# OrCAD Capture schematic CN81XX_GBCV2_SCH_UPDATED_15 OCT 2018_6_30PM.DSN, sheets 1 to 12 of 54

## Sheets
1 53.IO-EXPANDER: size B; title: IO-EXPANDER; rev: 1.0
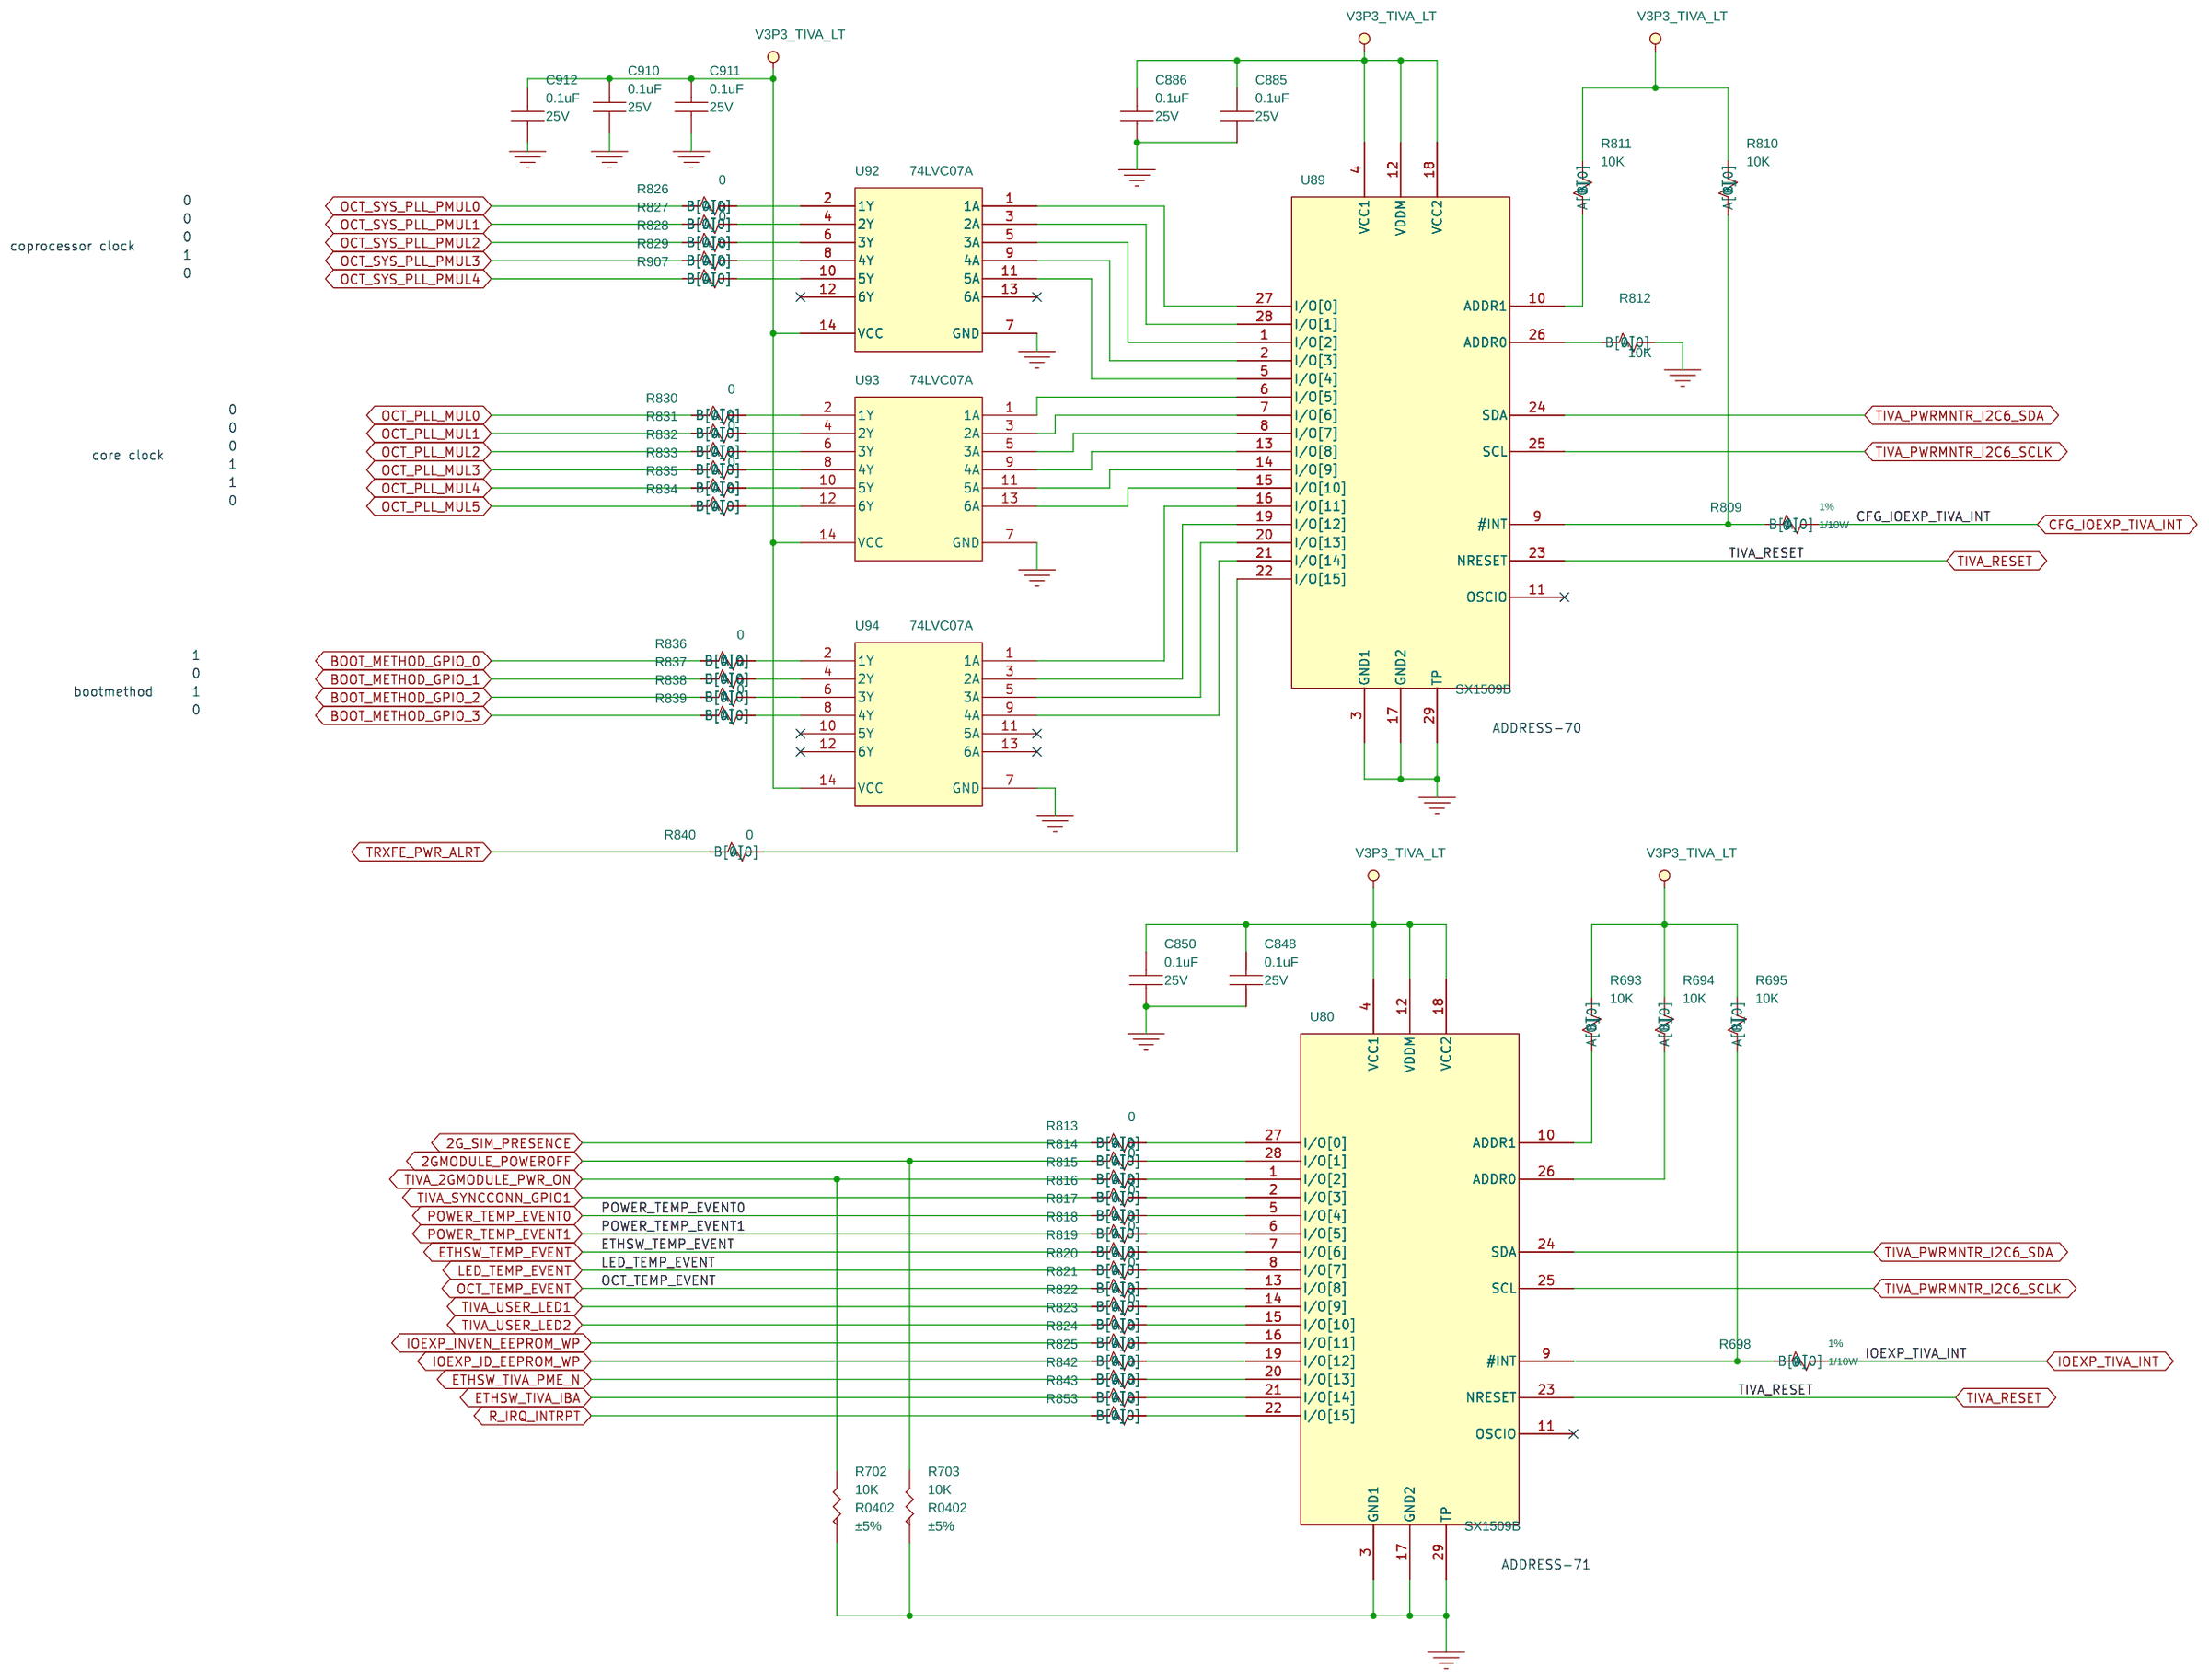
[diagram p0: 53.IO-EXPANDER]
2 54. SuperCap Back-Up: size A; title: TIVA BackUp Power
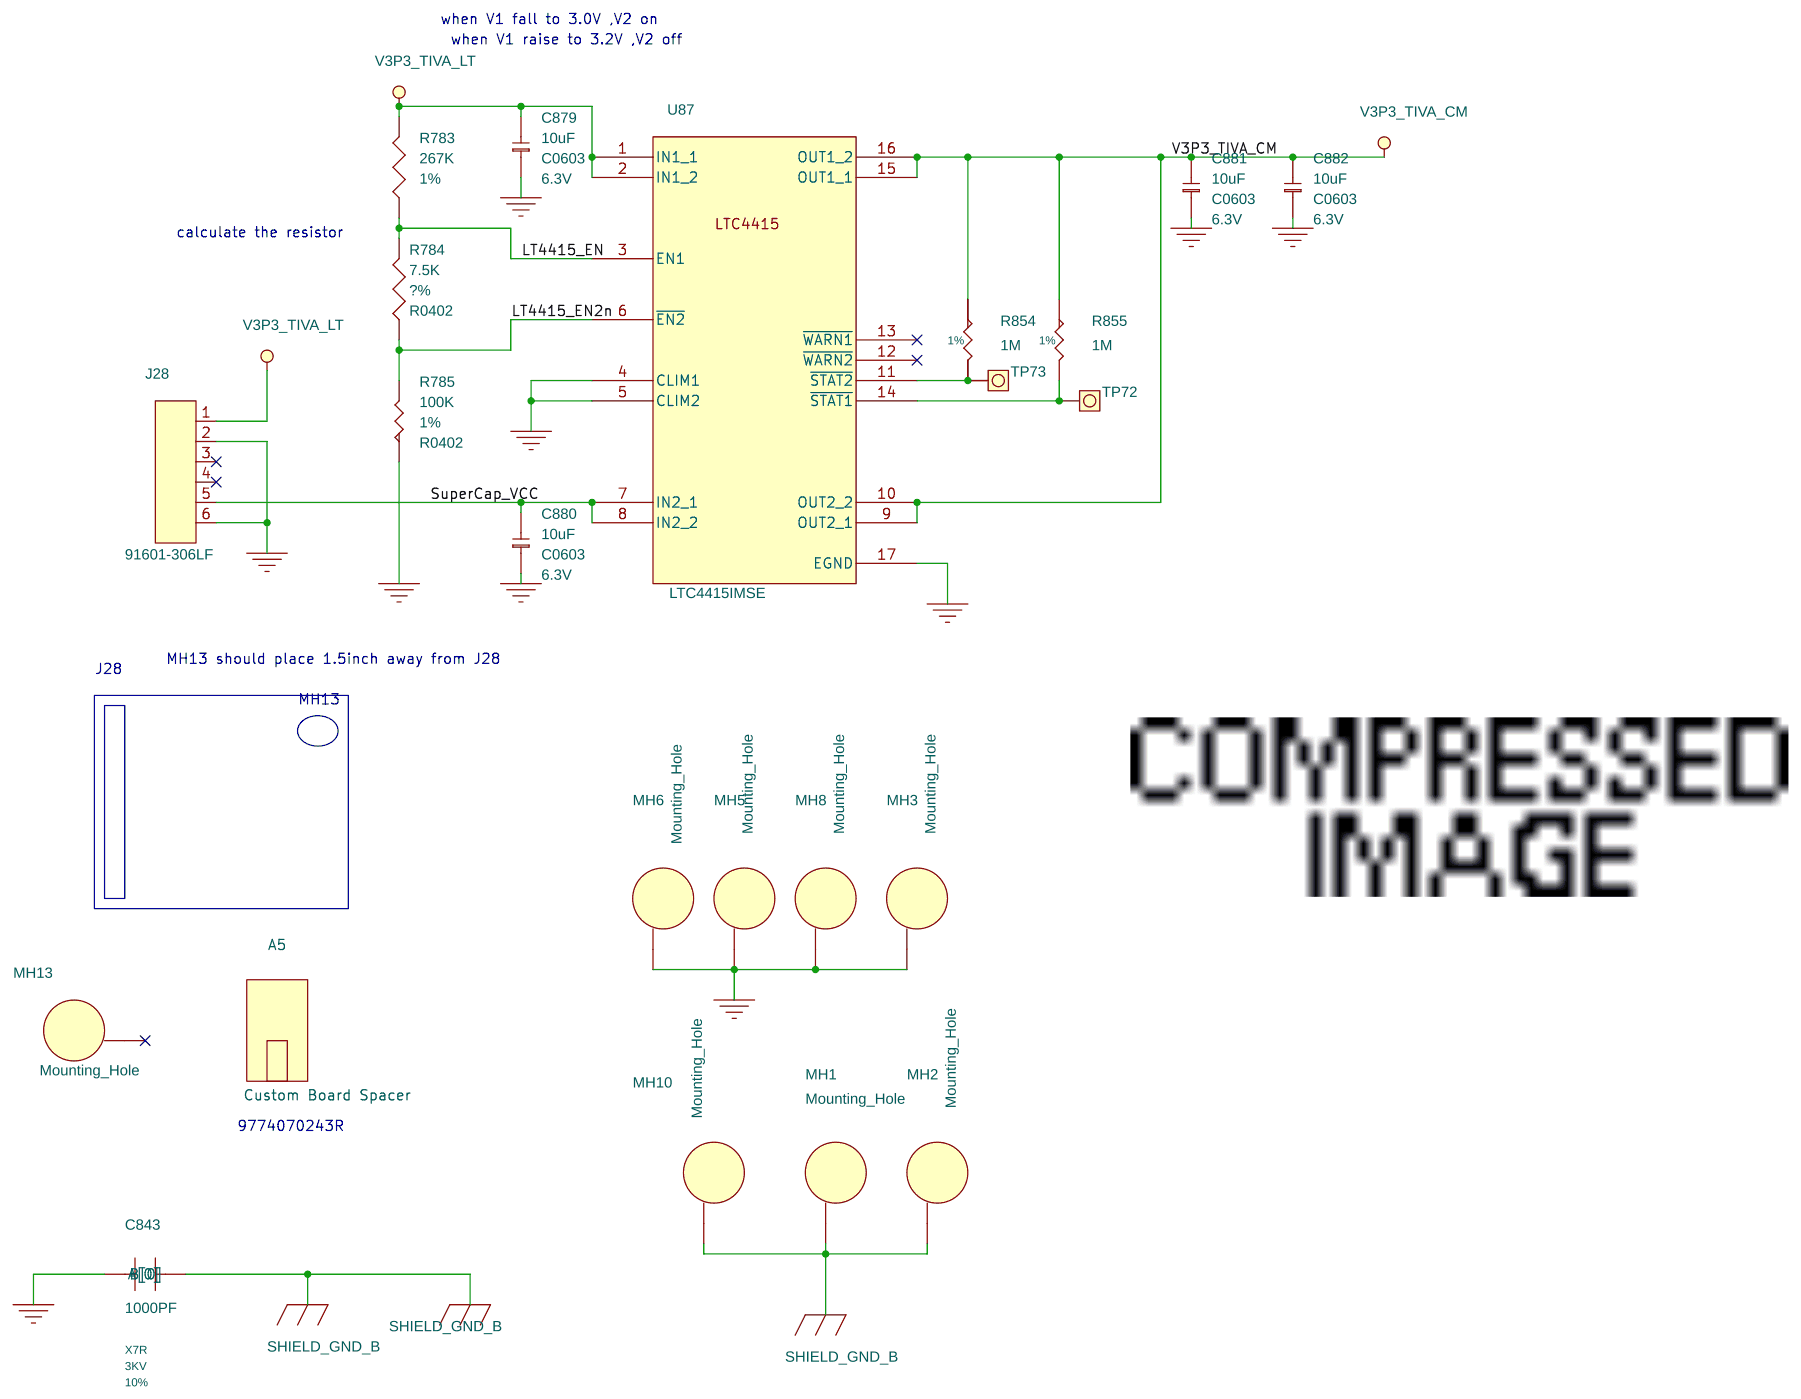
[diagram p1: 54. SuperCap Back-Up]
3 01.CN81XX COVER PAGE: title: CN81XX COVER PAGE
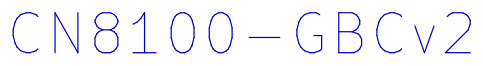
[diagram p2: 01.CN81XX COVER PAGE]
4 02.TABLE OF CONTENTS: title: TABLE OF CONTENTS
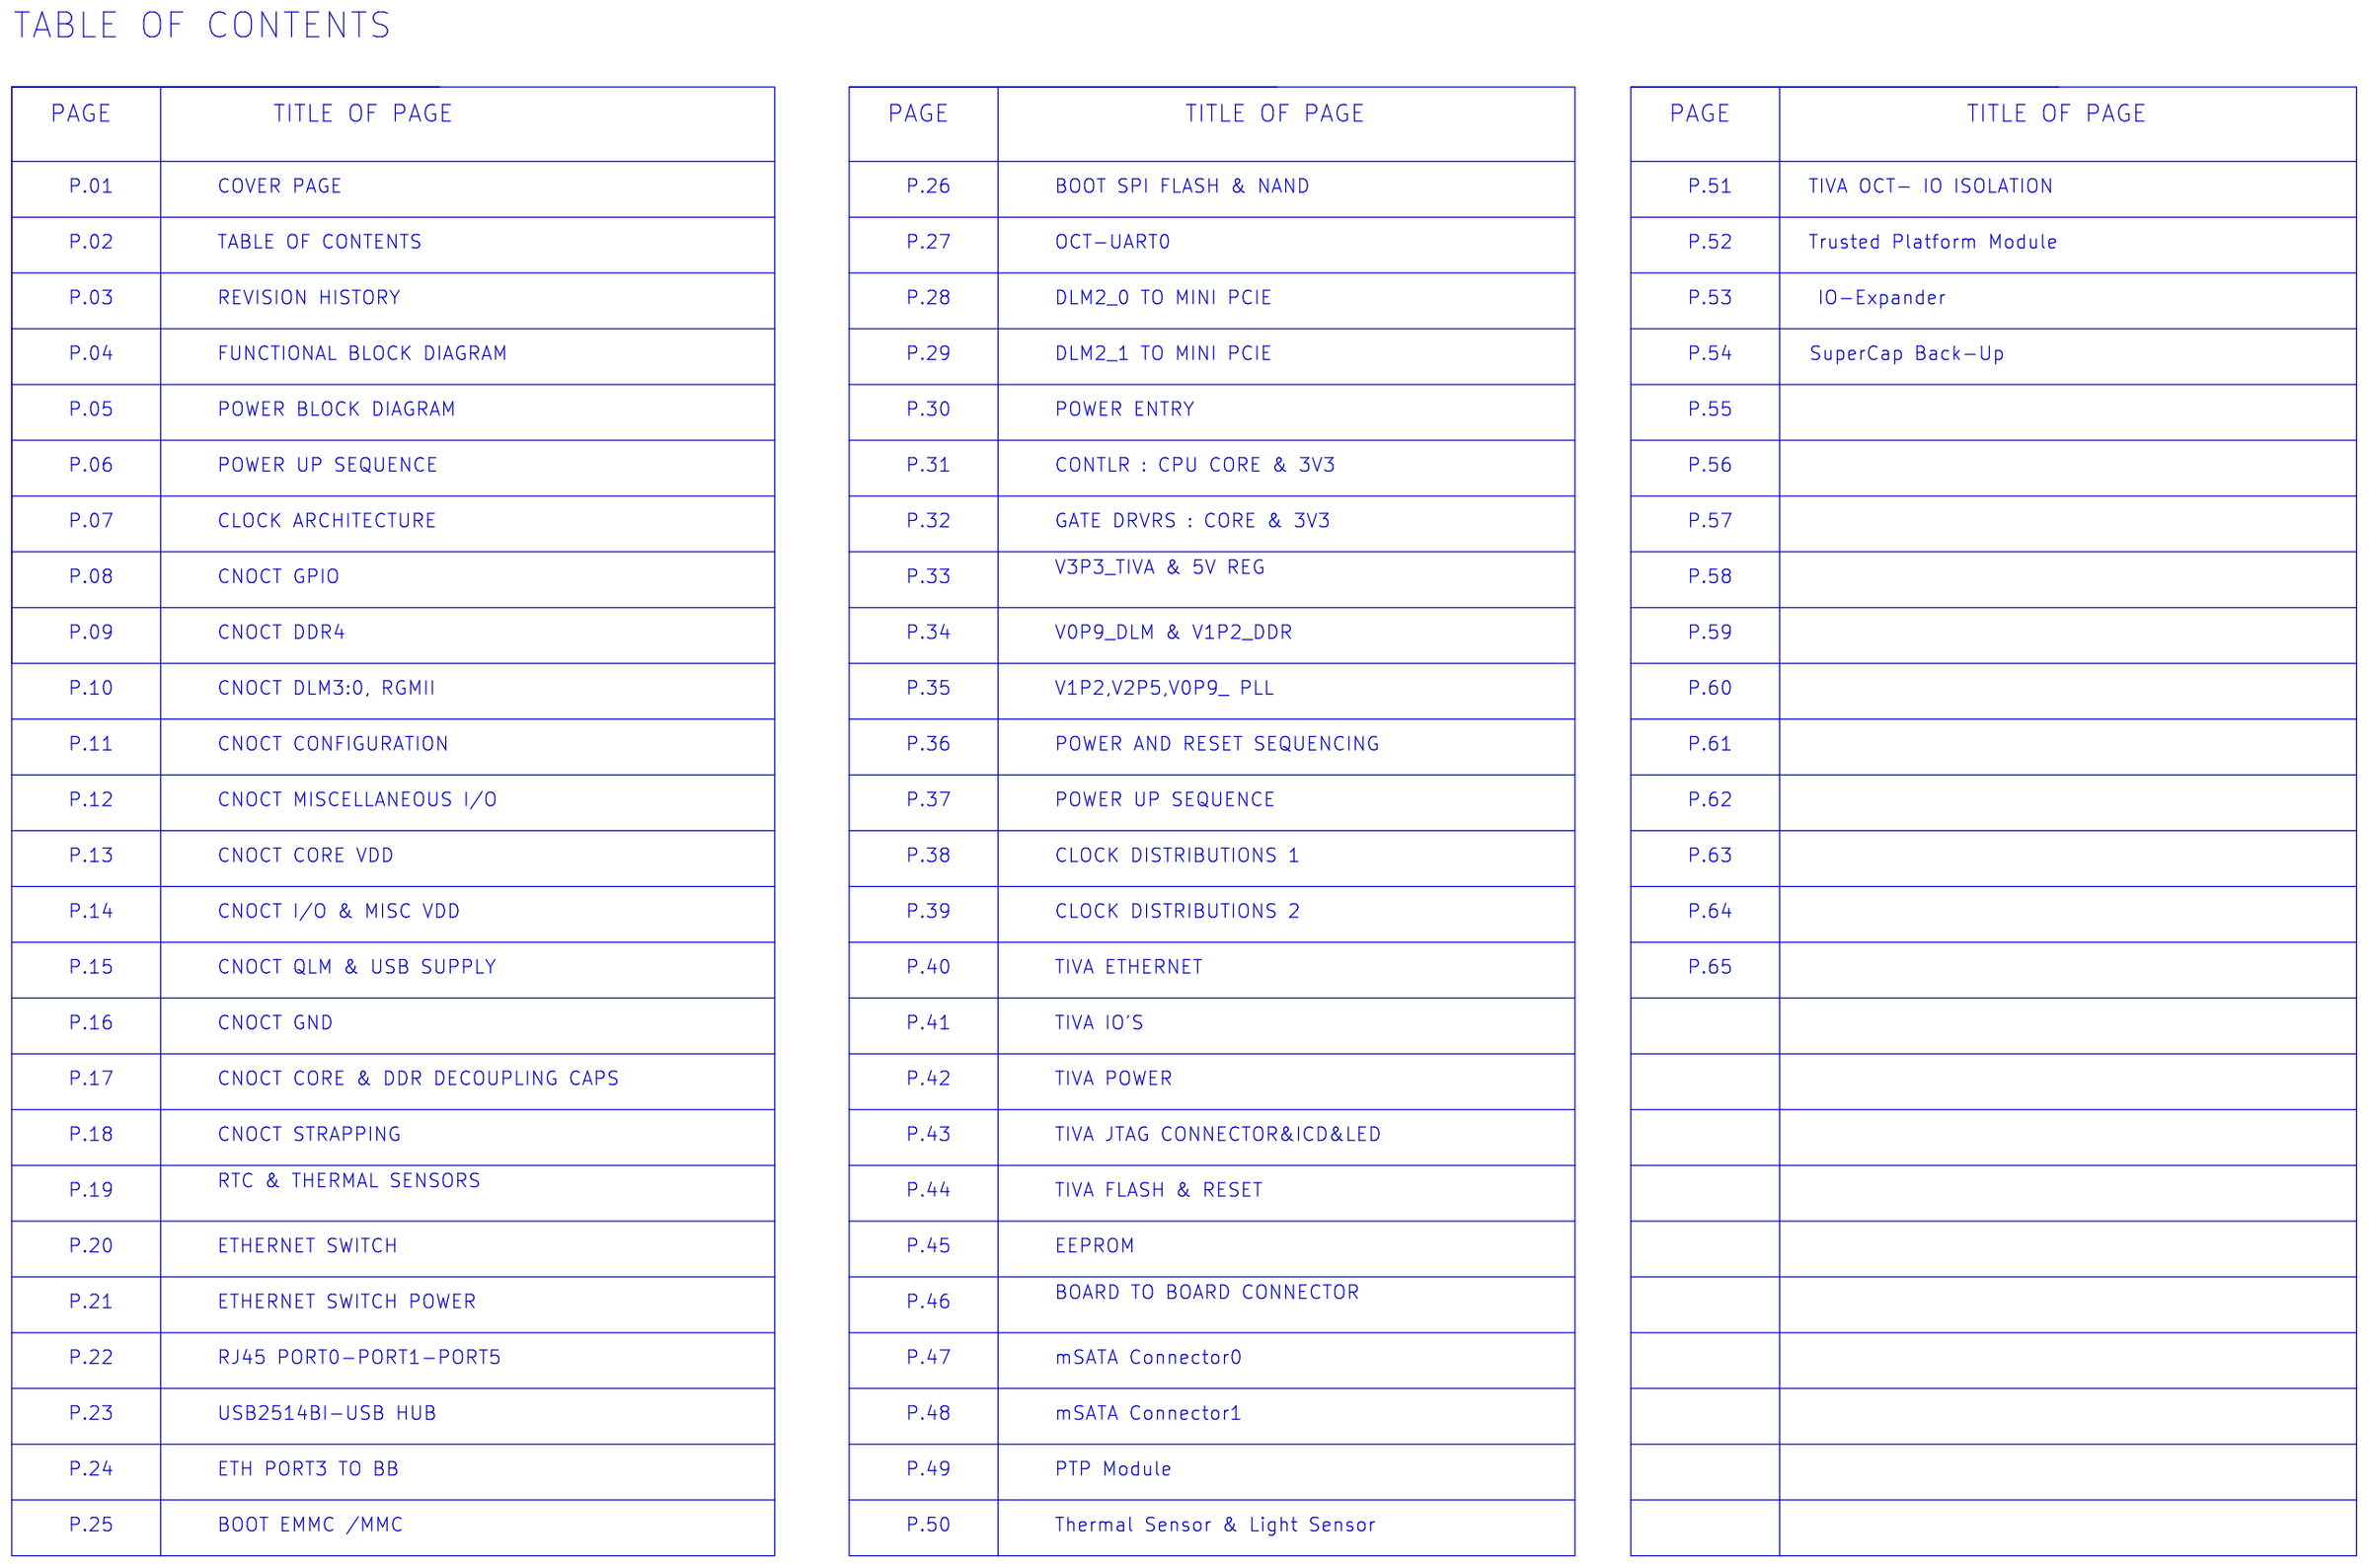
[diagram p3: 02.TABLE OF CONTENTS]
5 03.REVISION HISTORY: title: REVISION HISTORY
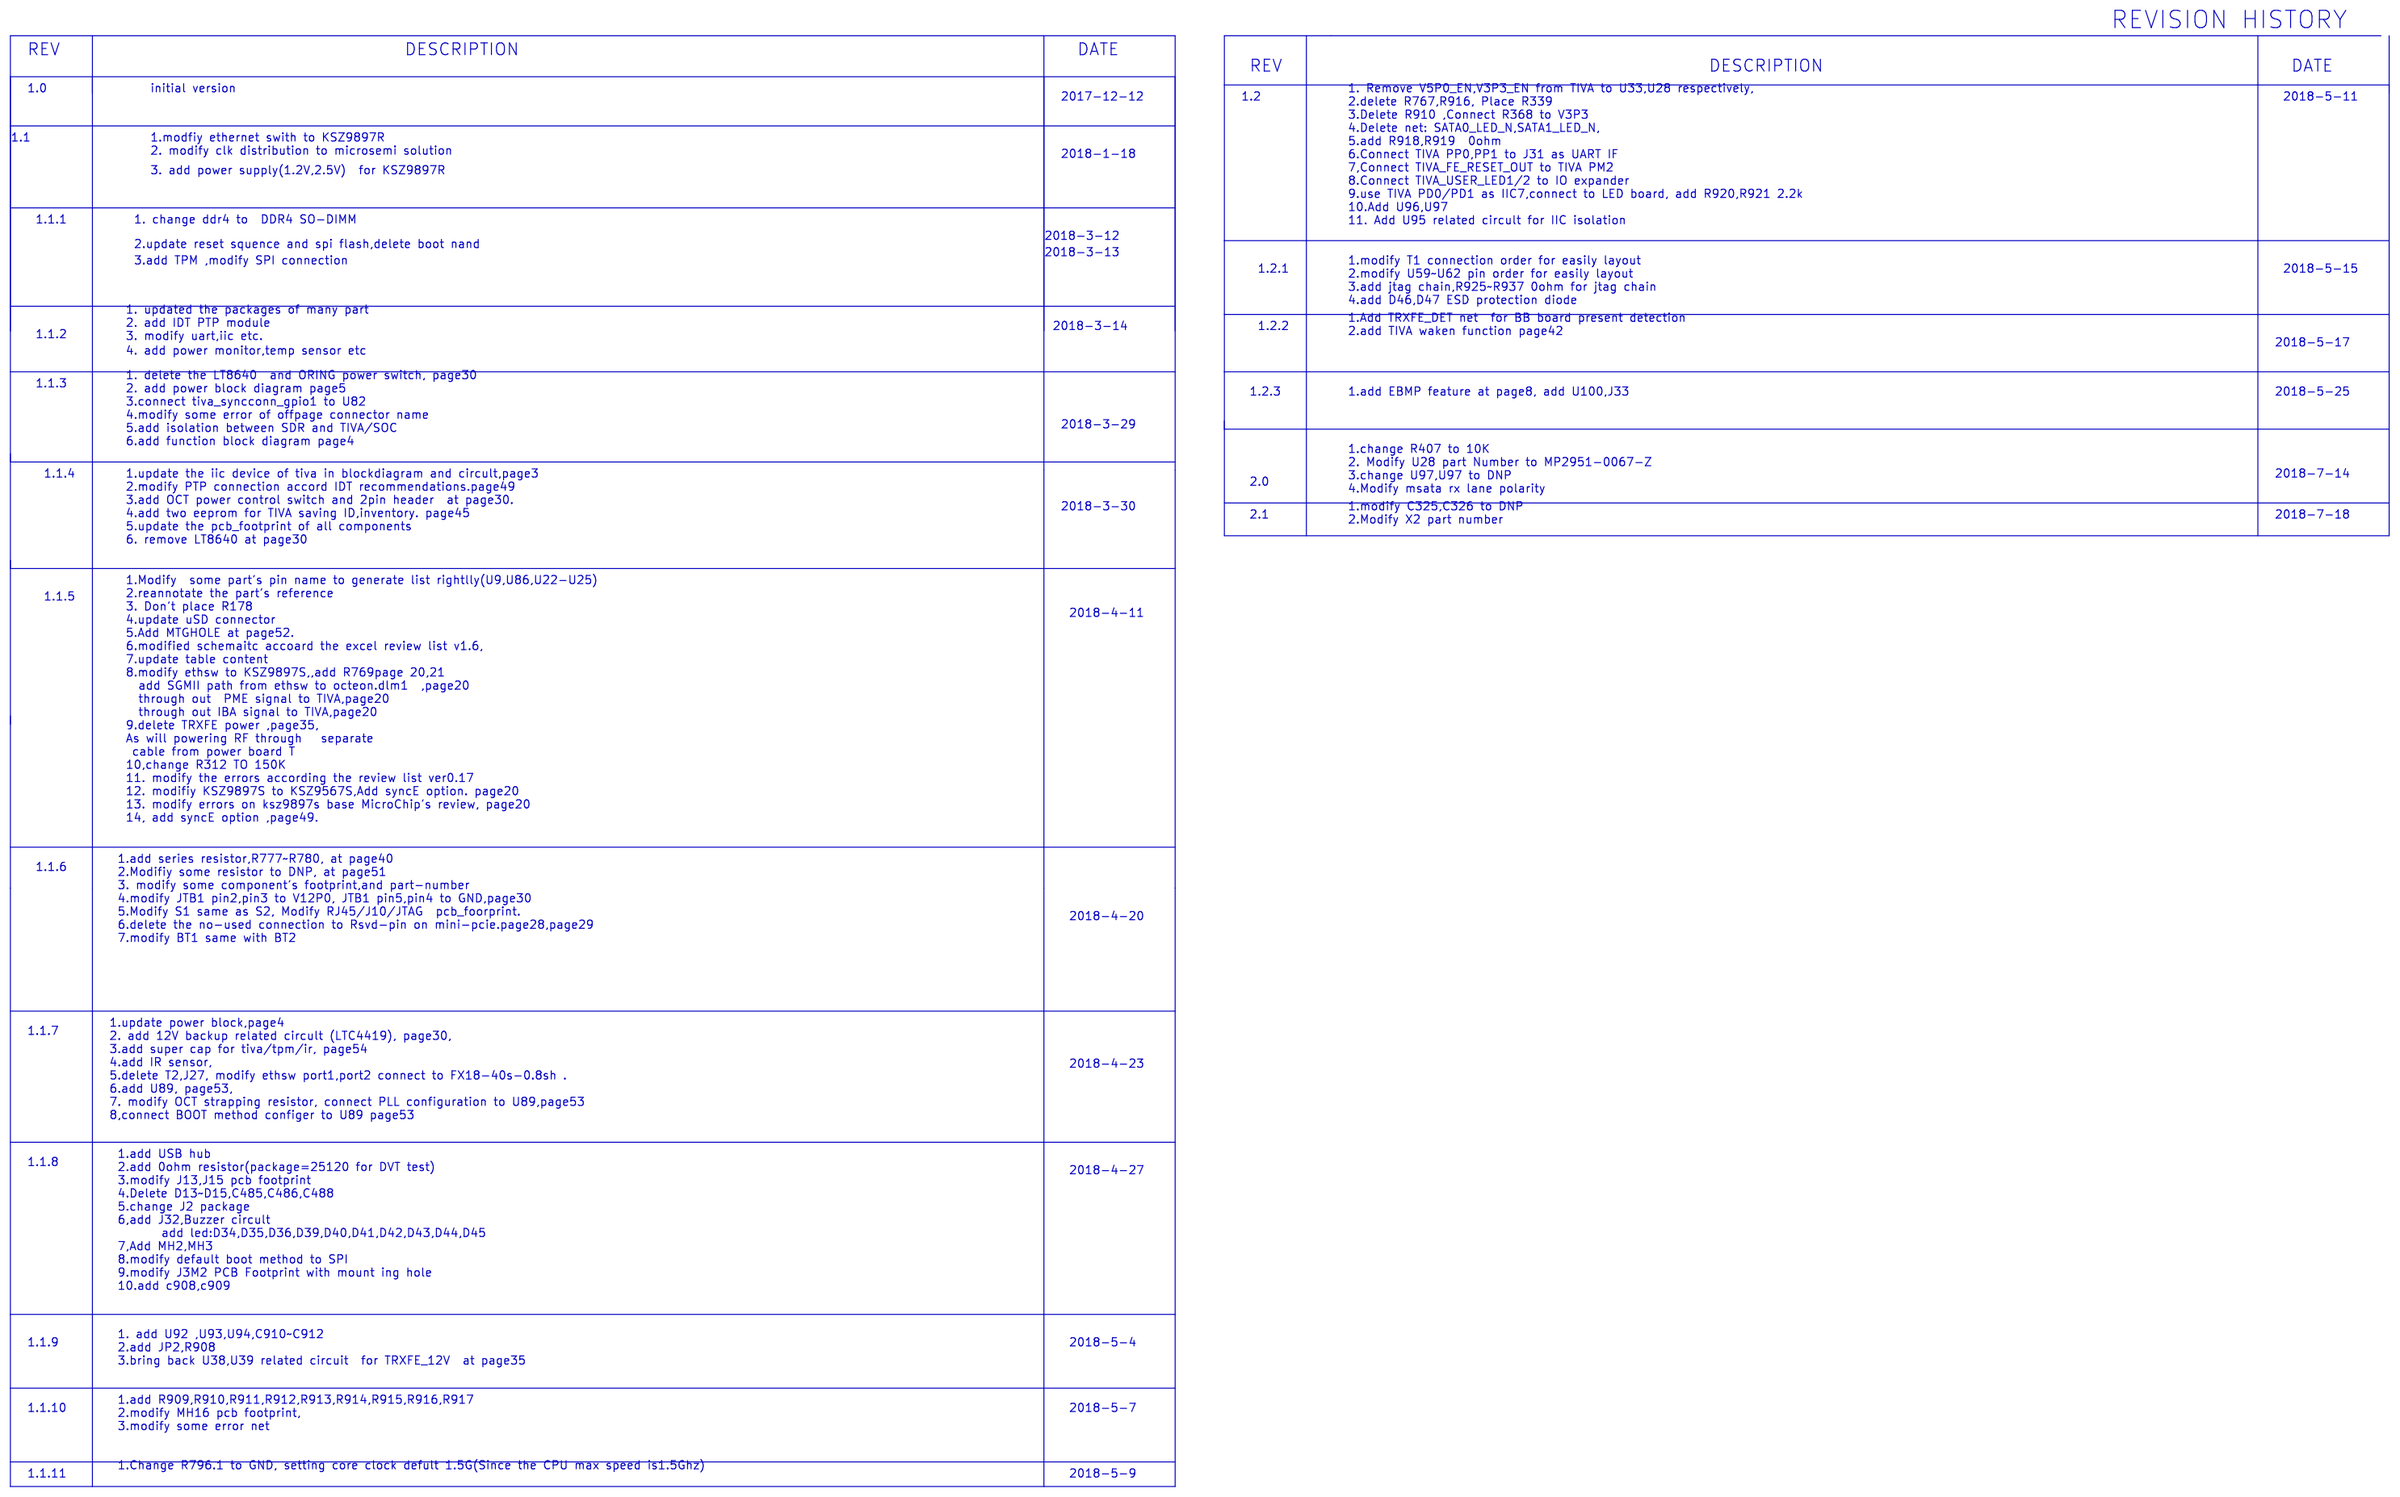
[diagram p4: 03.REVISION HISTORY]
6 04.FUNCTIONAL BLOCK DIAGRAM: title: FUNCTIONAL BLOCK DIAGRAM
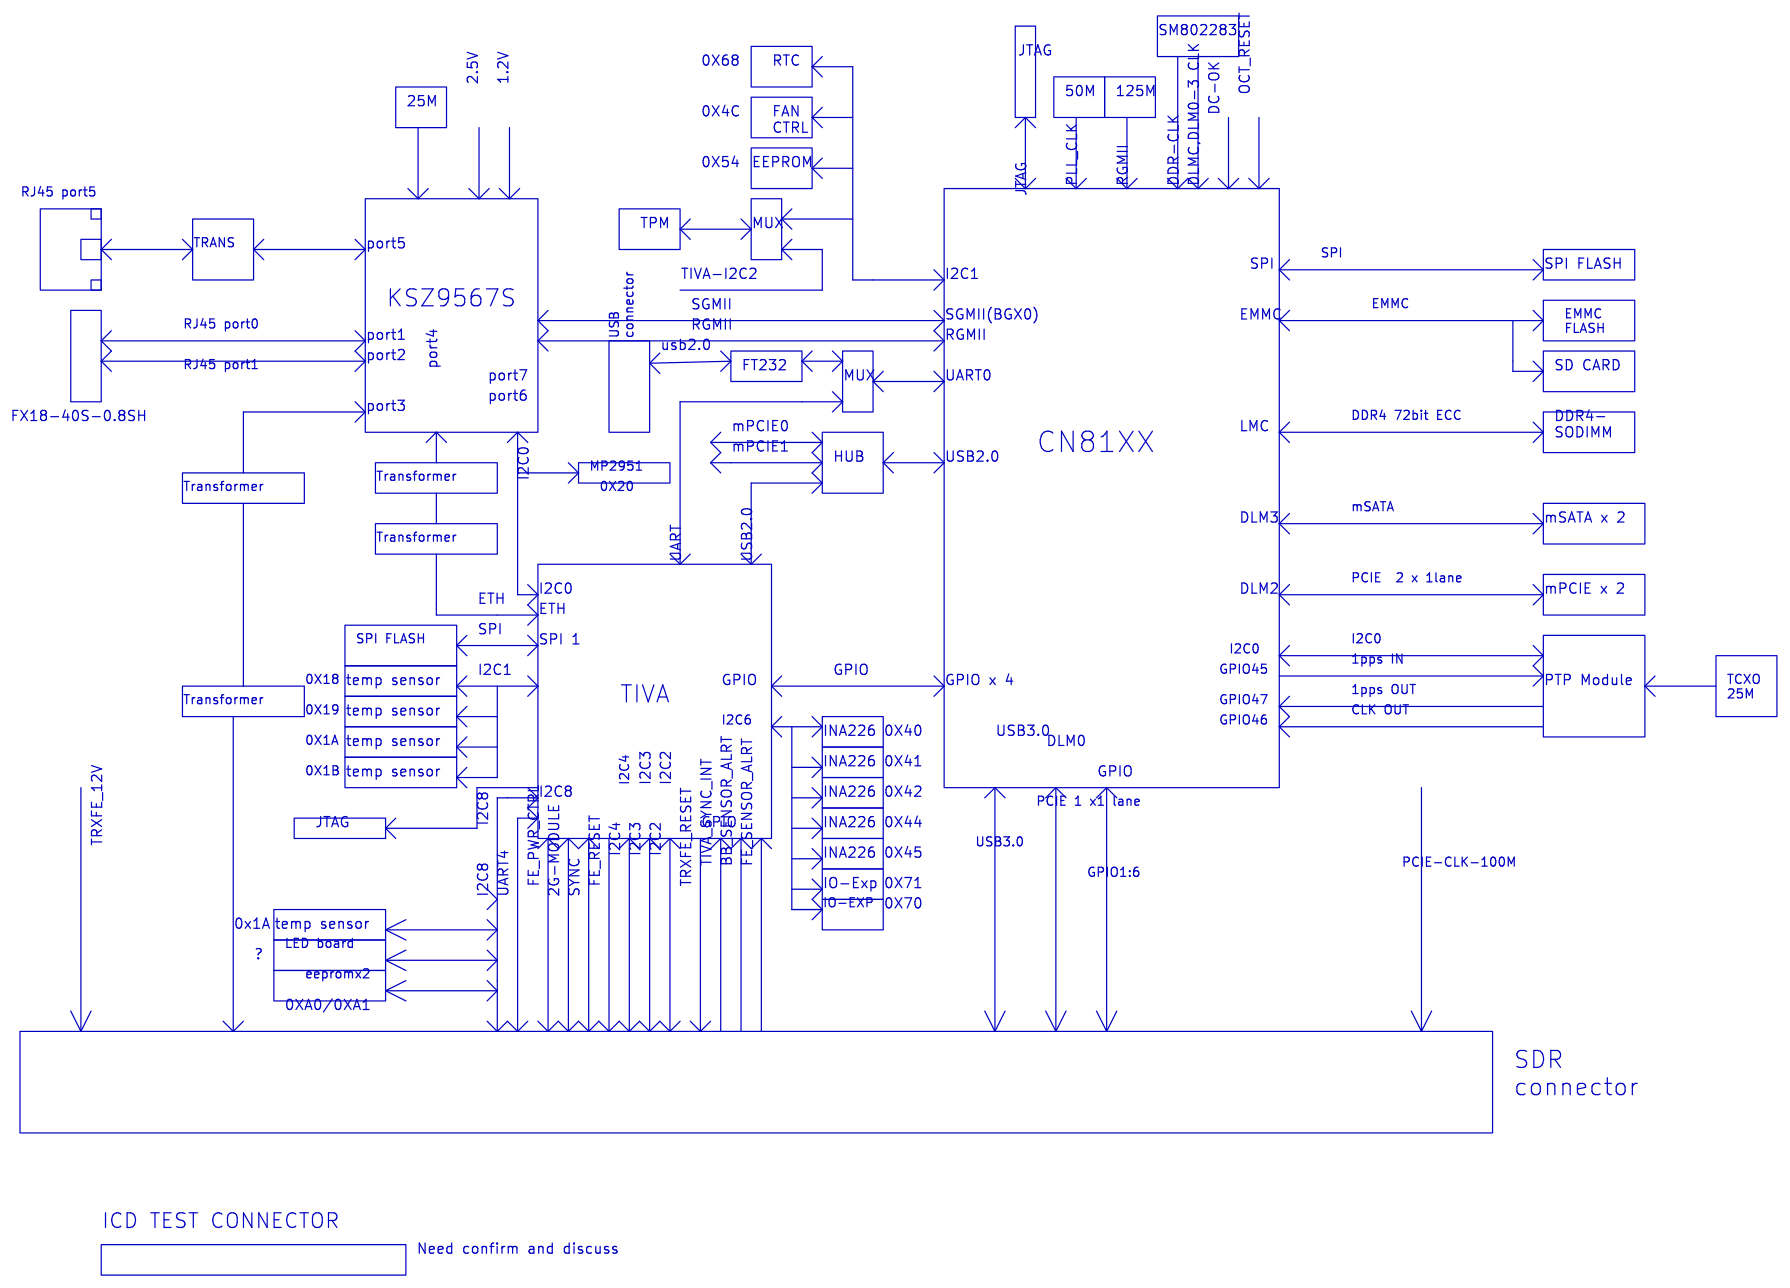
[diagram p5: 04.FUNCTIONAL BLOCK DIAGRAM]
7 05.POWER BLOCK DIAGRAM: title: POWER DIAGRAMS
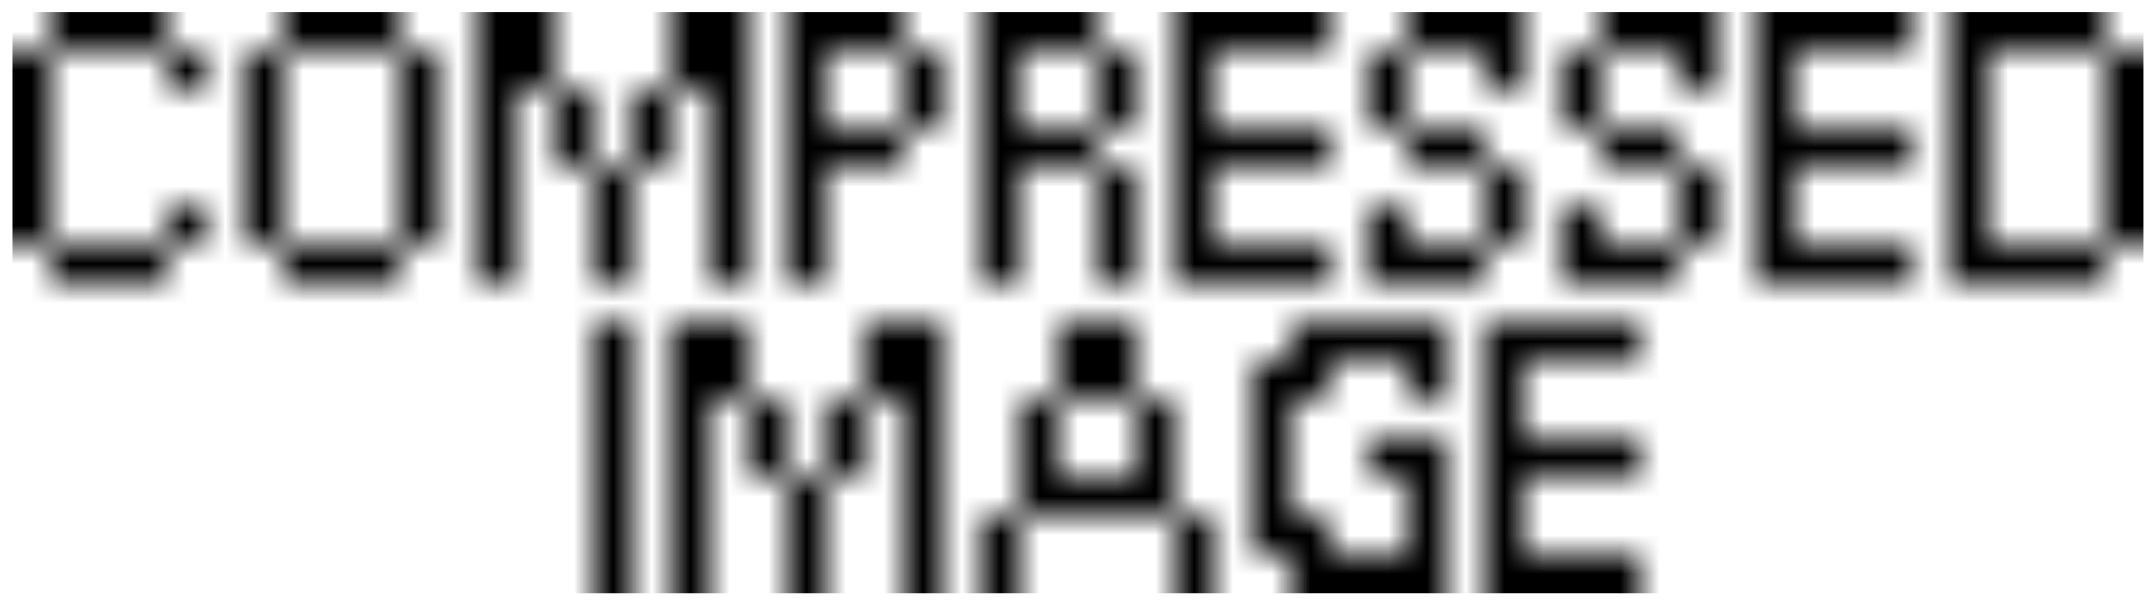
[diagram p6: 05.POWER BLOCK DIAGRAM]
8 06.POWER UP SEQUENCE: title: POWER UP SEQUENCE BLOCK
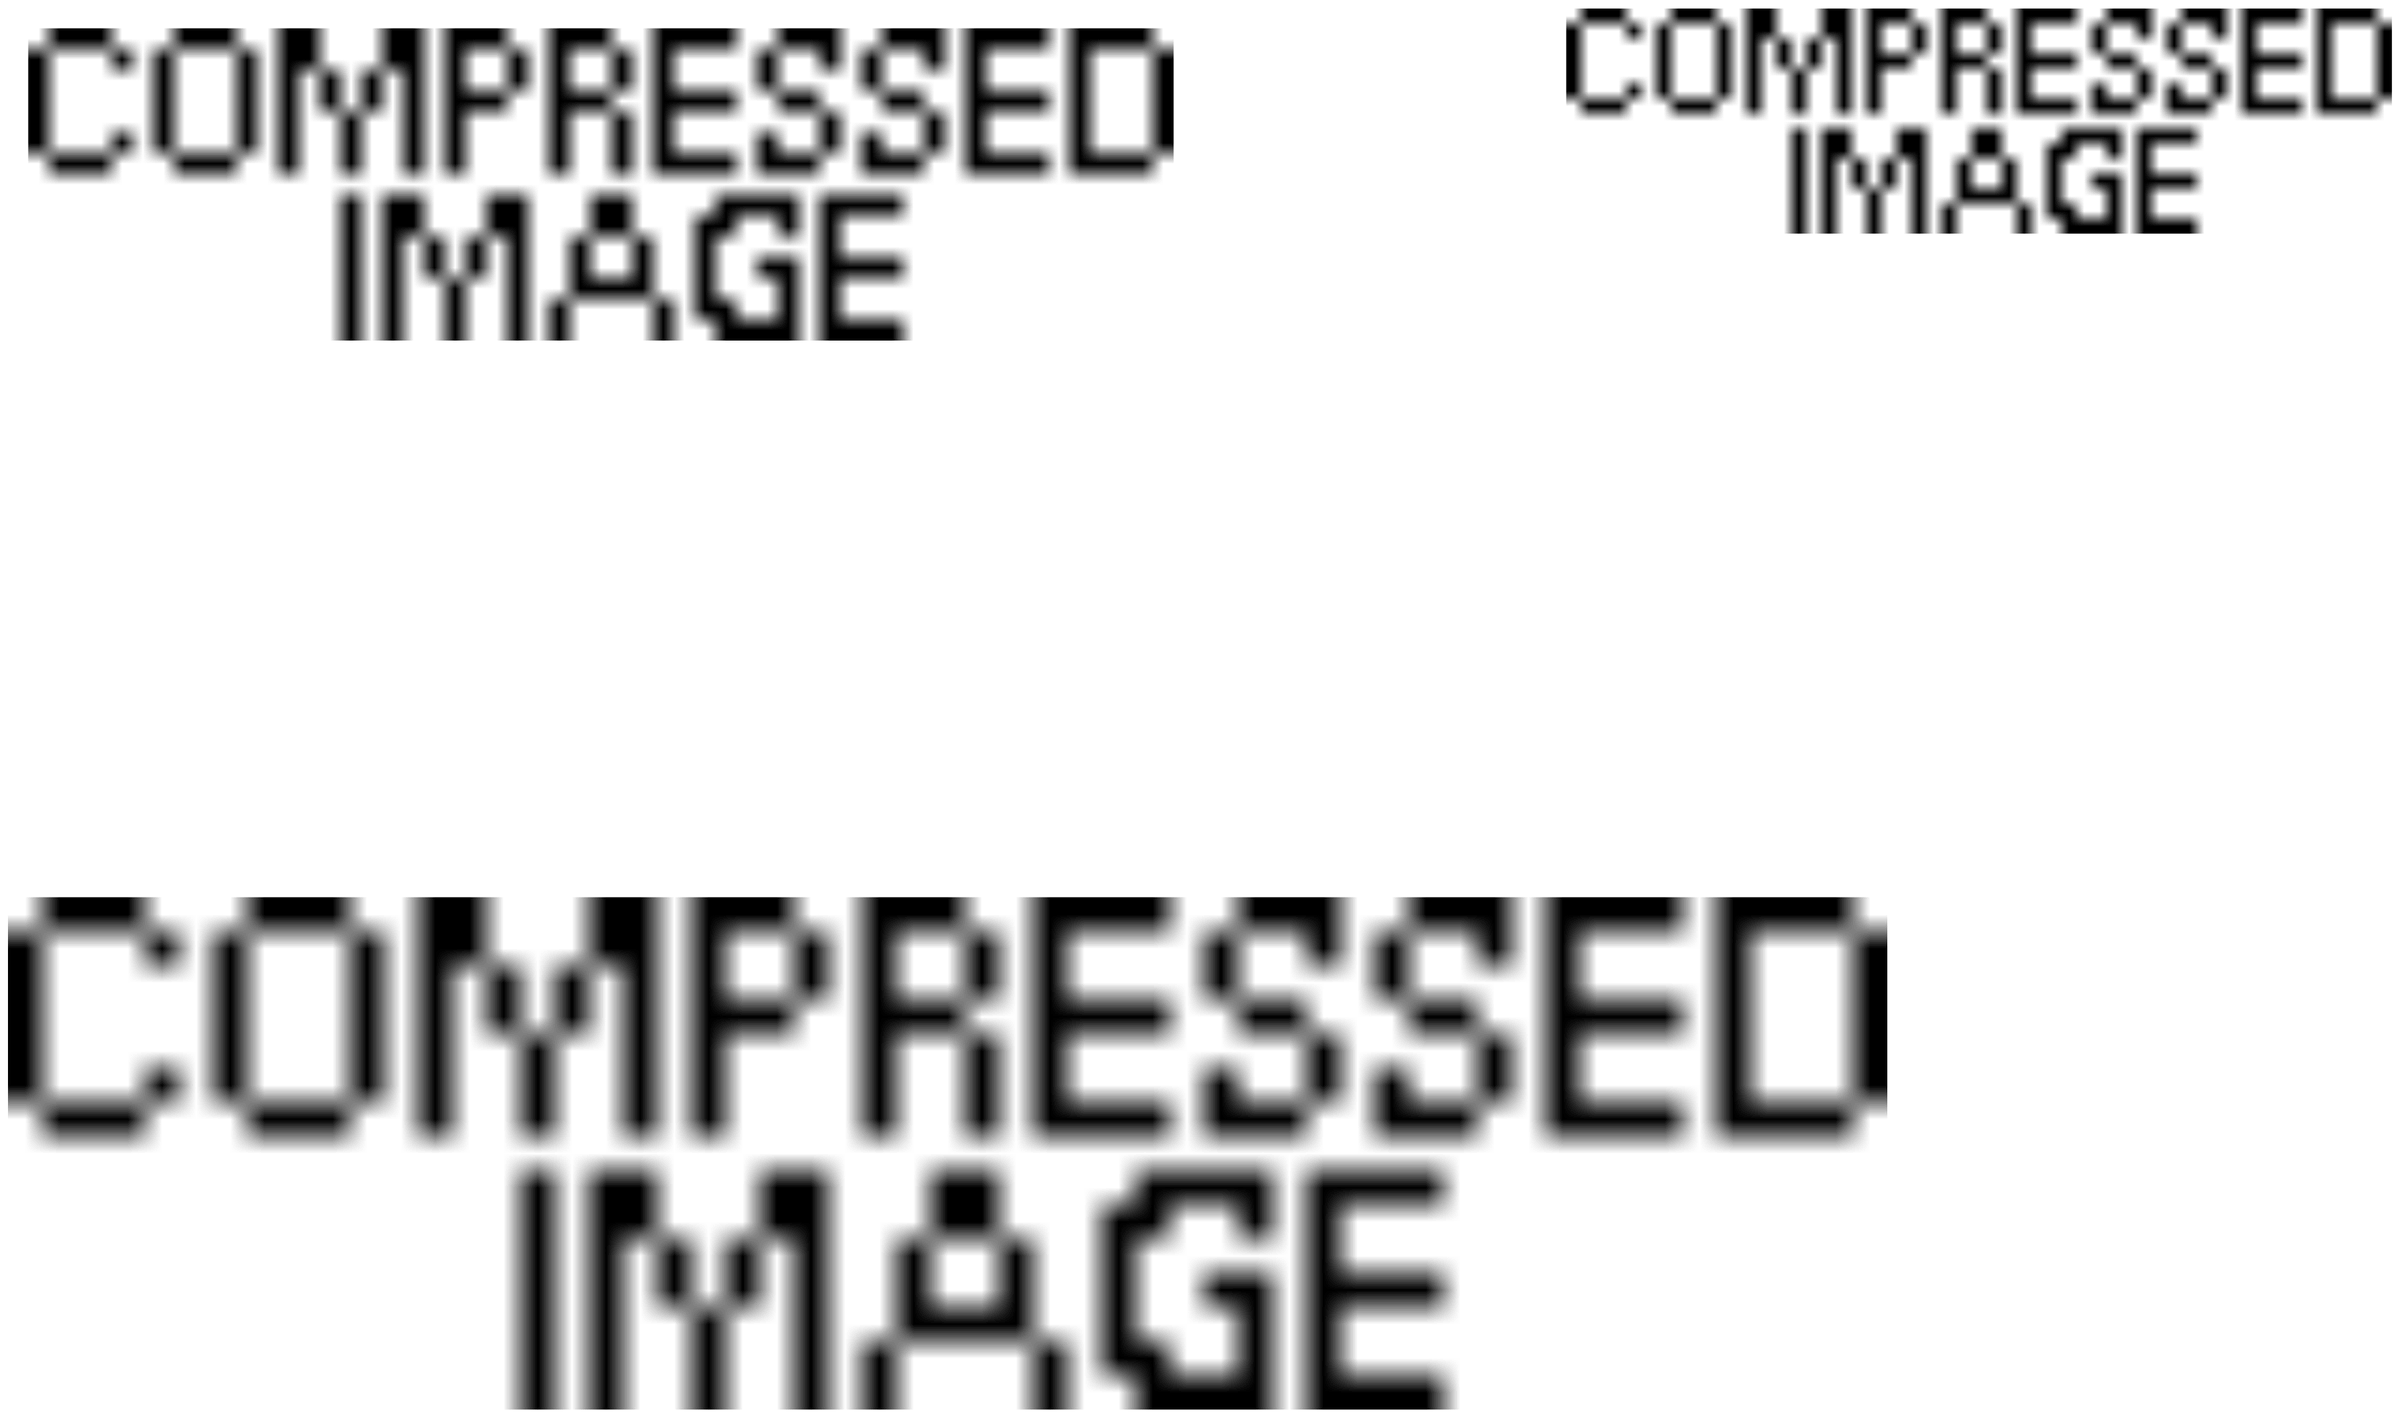
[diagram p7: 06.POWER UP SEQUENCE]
9 07.CLOCK ARCHITECTURE: title: CLOCK ARCHITECTURE
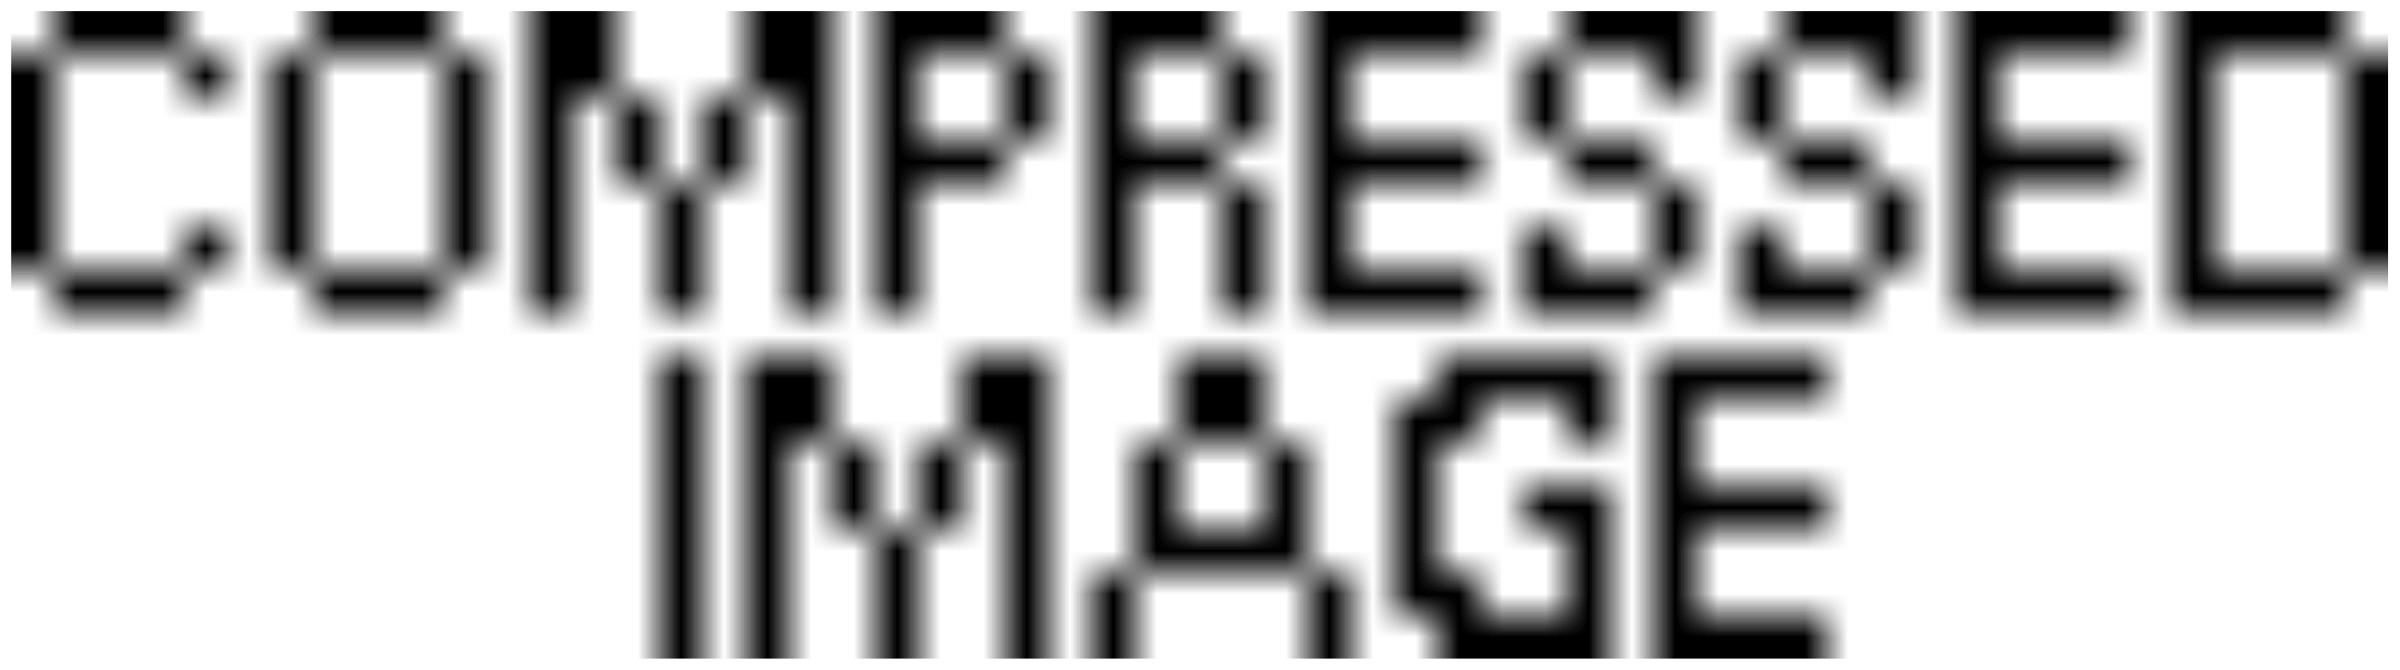
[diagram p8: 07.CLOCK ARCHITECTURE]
10 08.CN81XX GPIO: size B; title: CN81XX GPIO
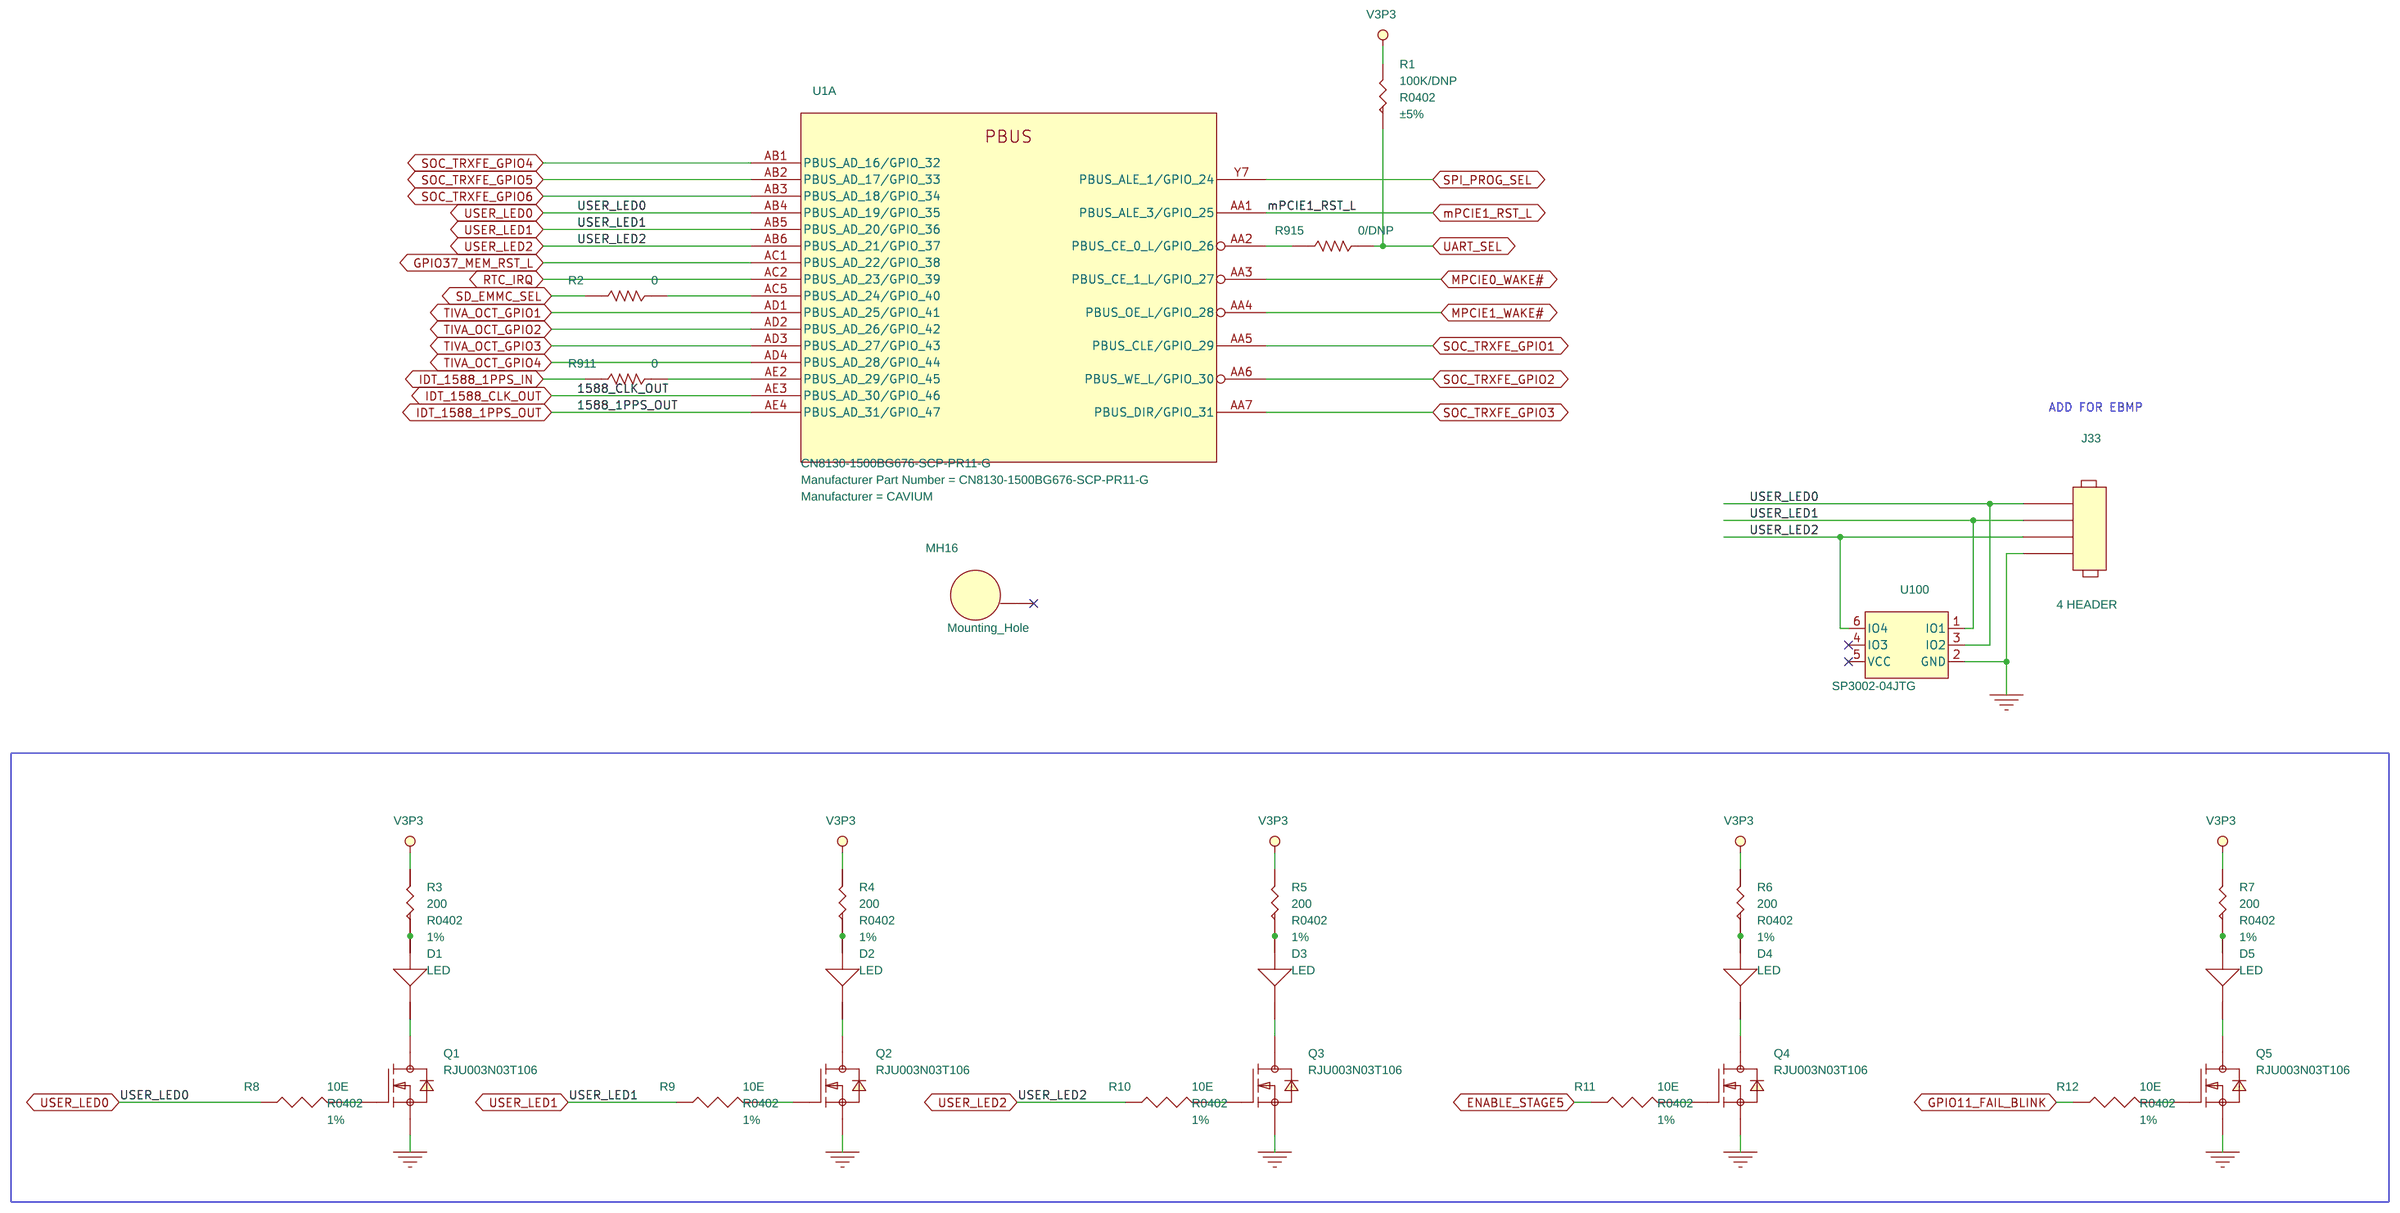
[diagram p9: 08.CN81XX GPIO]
11 09.CN81XX DDR4-SODIMM: size A2; title: CN81XX DDR4
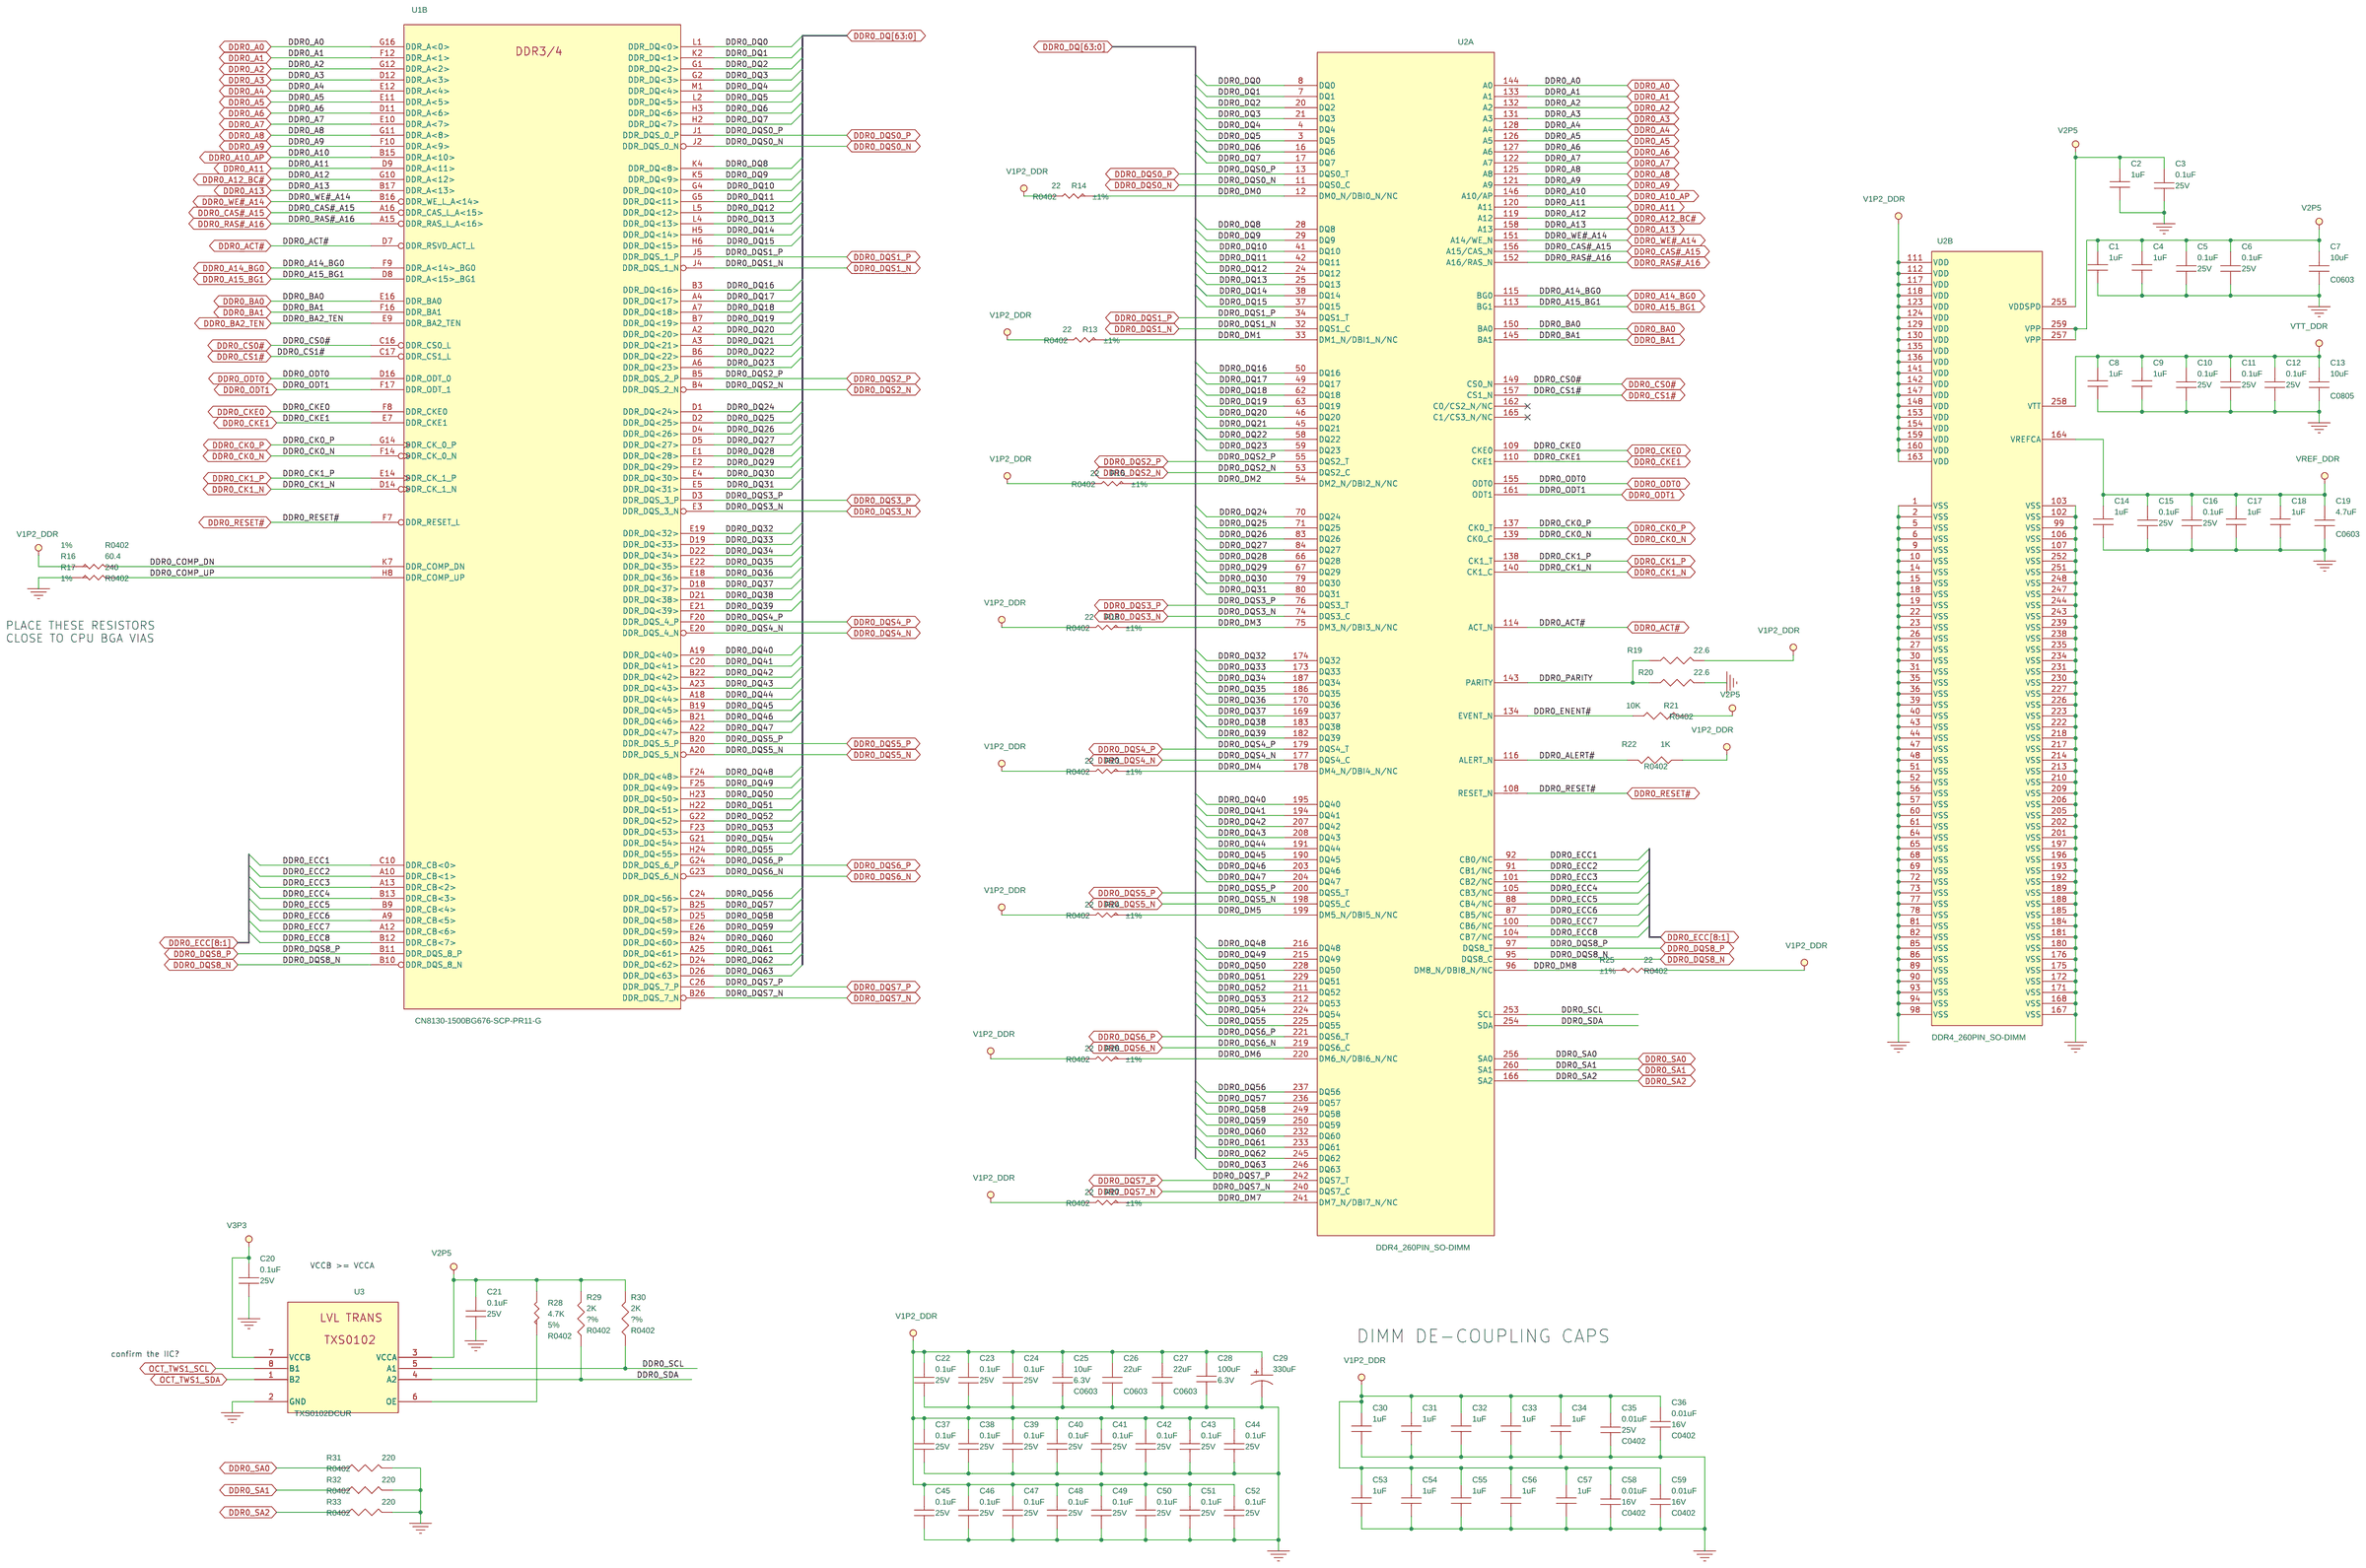
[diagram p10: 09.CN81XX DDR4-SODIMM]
12 11.CN81XX CONFIGURATION: size B; title: CN81XX CONFIGURATION
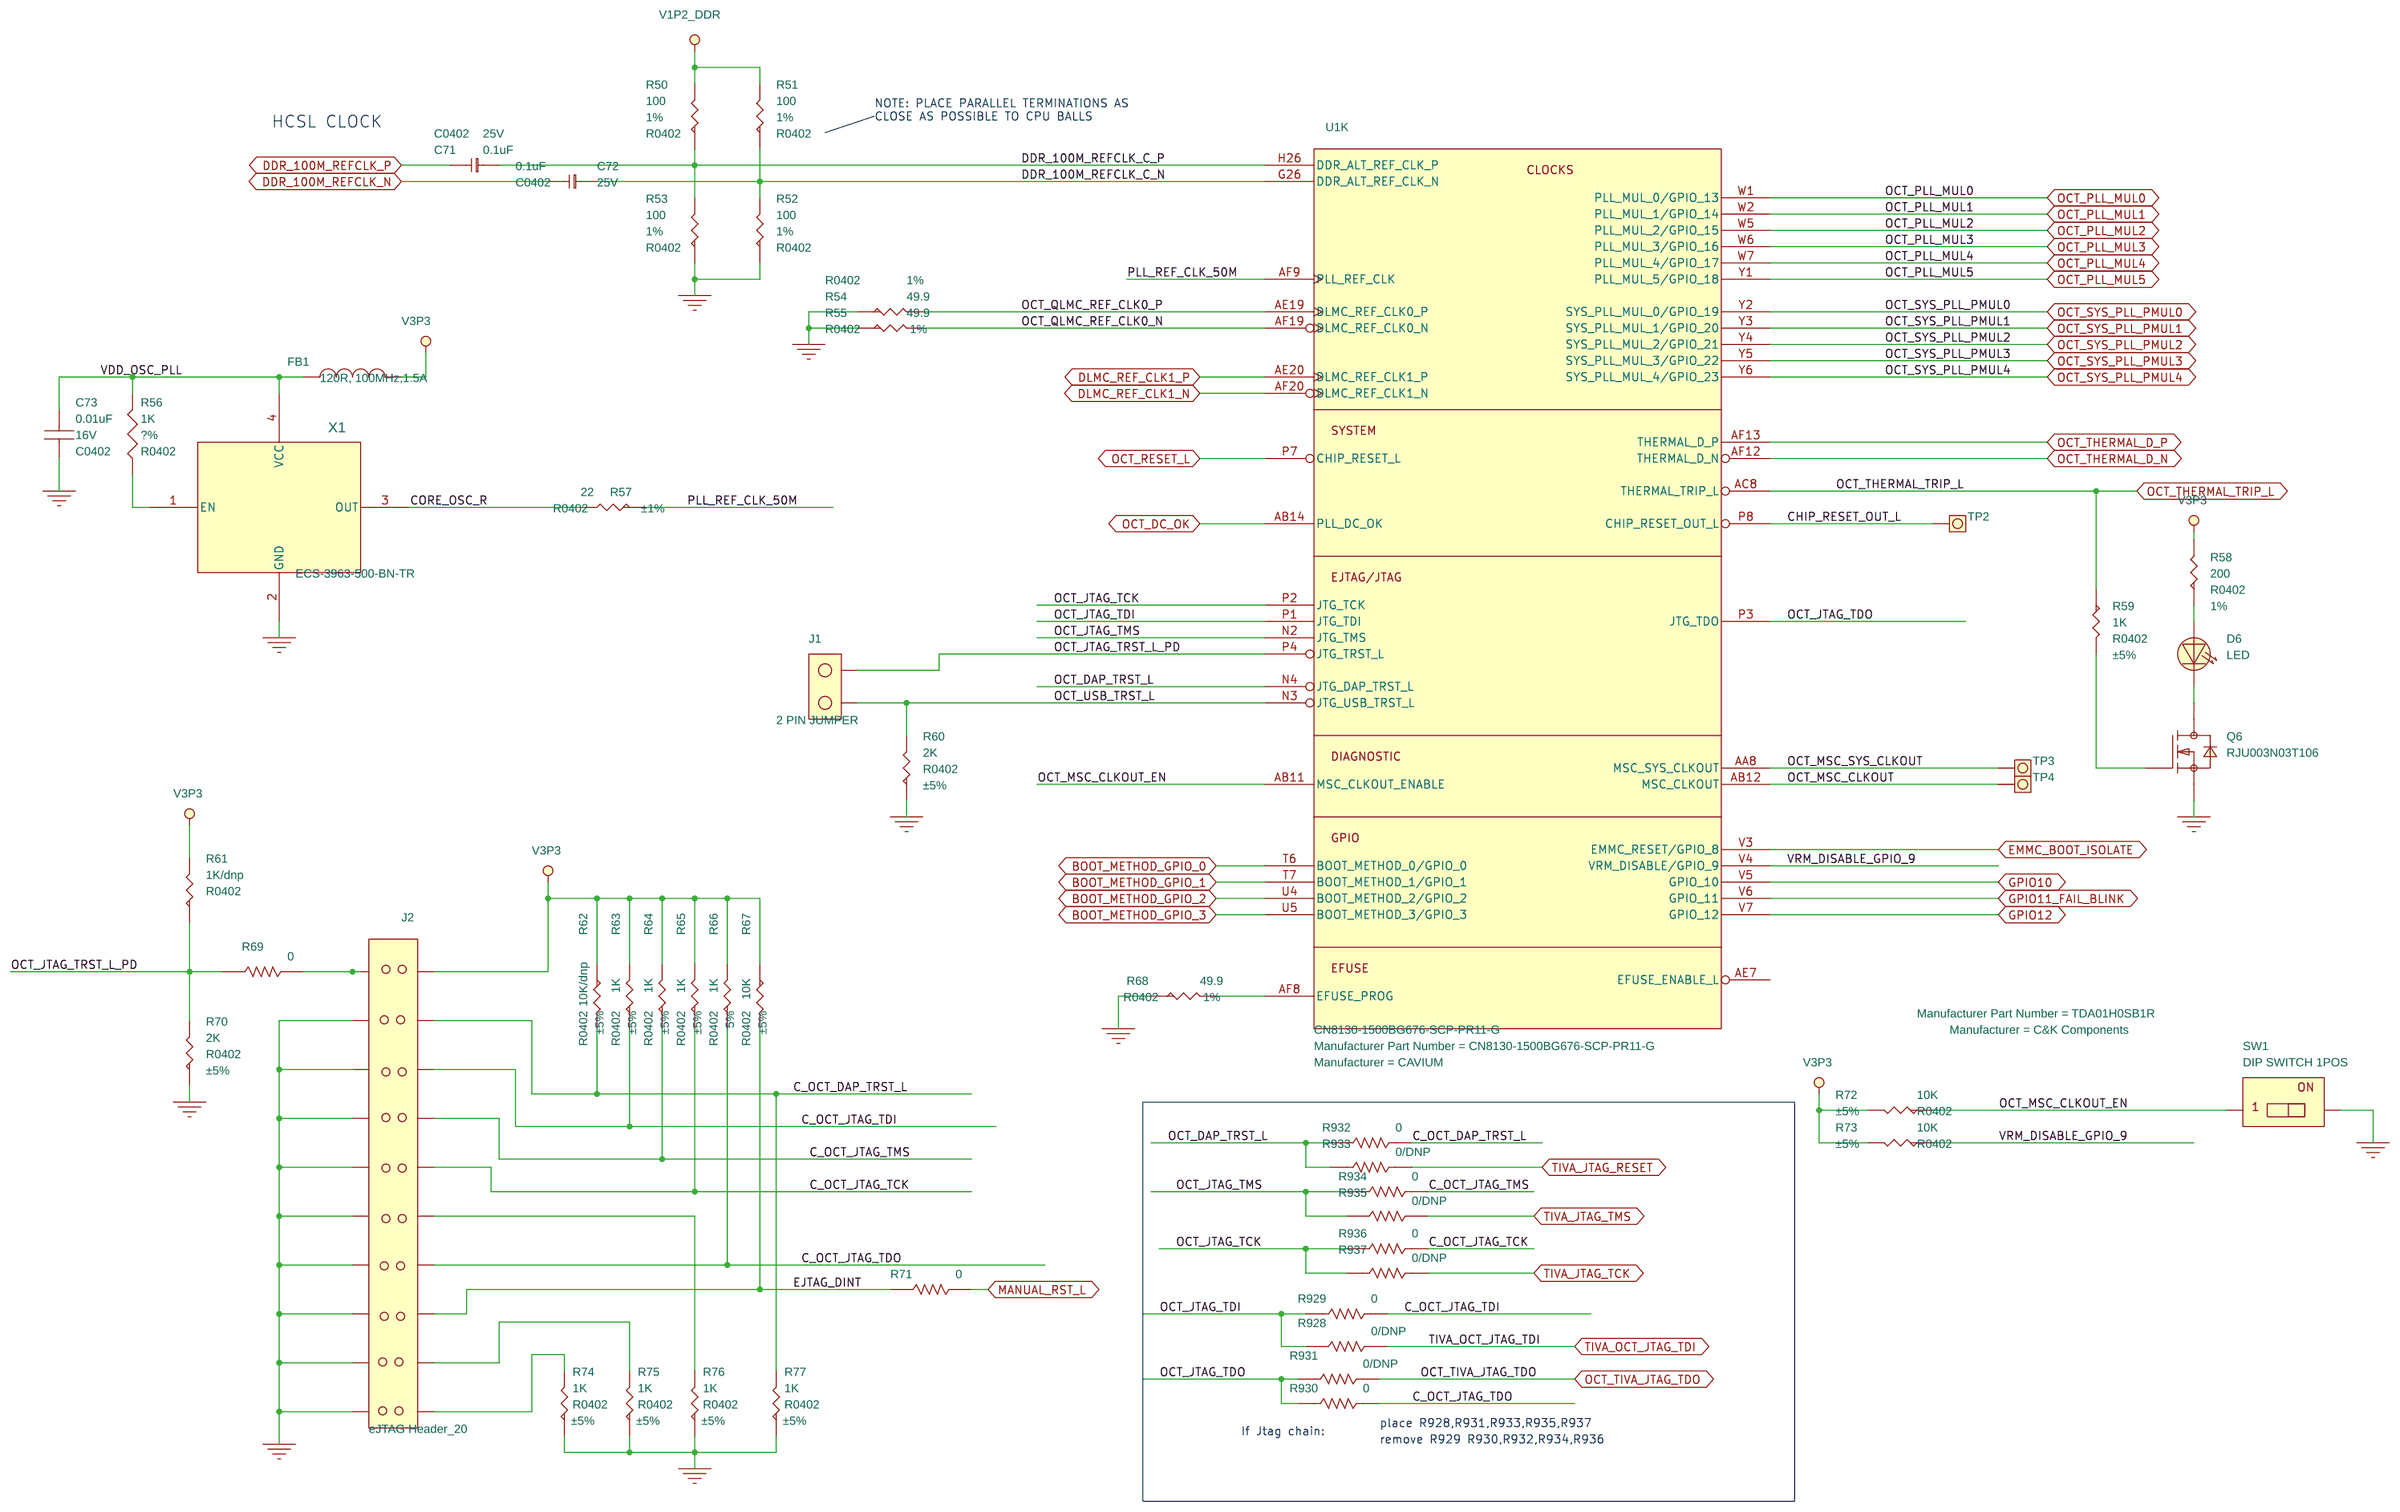
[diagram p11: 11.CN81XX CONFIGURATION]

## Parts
sheet 08.CN81XX GPIO
D1  LED  [LED_LTST-C190]
D2  LED  [LED_LTST-C190]
D3  LED  [LED_LTST-C190]
D4  LED  [LED_LTST-C190]
D5  LED  [LED_LTST-C190]
J33  4 HEADER  [SMDHD-2P54-4]
MH16  Mounting_Hole  [MTG370_800]
Q1  RJU003N03  [UMT3]
Q2  RJU003N03  [UMT3]
Q3  RJU003N03  [UMT3]
Q4  RJU003N03  [UMT3]
Q5  RJU003N03  [UMT3]
R1  100K/DNP  [R0402]
R2  0  [R0402]
R3  200  [R0402]
R4  200  [R0402]
R5  200  [R0402]
R6  200  [R0402]
R7  200  [R0402]
R8  10E  [R0402]
R9  10E  [R0402]
R10  10E  [R0402]
R11  10E  [R0402]
R12  10E  [R0402]
R911  0  [R0402]
R915  0/DNP  [R0402]
U100  SP3002-04JTG  [SC70-6]
sheet 09.CN81XX DDR4-SODIMM
C1  1uF  [C0402]
C2  1uF  [C0402]
C3  0.1uF  [C0402]
C4  1uF  [C0402]
C5  0.1uF  [C0402]
C6  0.1uF  [C0402-BGA]
C7  10uF  [C0603]
C8  1uF  [C0402]
C9  1uF  [C0402]
C10  0.1uF  [C0402]
C11  0.1uF  [C0402]
C12  0.1uF  [C0402]
C13  10uF  [C0805]
C14  1uF  [C0402]
C15  0.1uF  [C0402]
C16  0.1uF  [C0402]
C17  1uF  [C0402]
C18  1uF  [C0402]
C19  4.7uF  [C0603]
C20  0.1uF  [C0402]
C21  0.1uF  [C0402]
C22  0.1uF  [C0402]
C23  0.1uF  [C0402]
C24  0.1uF  [C0402]
C25  10uF  [C0603]
C26  22uF  [C0603]
C27  22uF  [C0603]
C28  100uF  [C1210]
C29  330uF  [CT7343]
C30  1uF  [C0402]
C31  1uF  [C0402]
C32  1uF  [C0402]
C33  1uF  [C0402]
C34  1uF  [C0402]
C35  0.01uF  [C0402]
C36  0.01uF  [C0402]
C37  0.1uF  [C0402]
C38  0.1uF  [C0402]
C39  0.1uF  [C0402]
C40  0.1uF  [C0402-BGA]
C41  0.1uF  [C0402]
C42  0.1uF  [C0402]
C43  0.1uF  [C0402]
C44  0.1uF  [C0402]
C45  0.1uF  [C0402]
C46  0.1uF  [C0402]
C47  0.1uF  [C0402]
C48  0.1uF  [C0402]
C49  0.1uF  [C0402]
C50  0.1uF  [C0402]
C51  0.1uF  [C0402]
C52  0.1uF  [C0402]
C53  1uF  [C0402]
C54  1uF  [C0402]
C55  1uF  [C0402]
C56  1uF  [C0402]
C57  1uF  [C0402]
C58  0.01uF  [C0402]
C59  0.01uF  [C0402]
R13  22  [R0402]
R14  22  [R0402]
R15  22  [R0402]
R16  60.4  [R0402]
R17  240  [R0402]
R18  22  [R0402]
R19  22.6  [R0402]
R20  22.6  [R0402]
R21  10K  [R0402]
R22  1K  [R0402]
R23  22  [R0402]
R24  22  [R0402]
R25  22  [R0402]
R26  22  [R0402]
R27  22  [R0402]
R28  4.7K  [R0402]
R29  2K  [R0402]
R30  2K  [R0402]
R31  220  [R0402]
R32  220  [R0402]
R33  220  [R0402]
U2  DDR4_260PIN_SO-DIMM  [DDR4-SO-DIMM-260]  (sections A,B)
U3  TXS0102DCUR  [SOP8_0O5MM_2O3MM_H0O9_TI]
sheet 11.CN81XX CONFIGURATION
C71  0.1uF  [C0402]
C72  0.1uF  [C0402]
C73  0.01uF  [C0402]
D6  LED  [D0603]
FB1  120R, 100MHz,1.5A  [L0402]
J1  2 PIN JUMPER  [HDR_1X2]
J2  eJTAG Header_20  [M50-3601042]
Q6  RJU003N03  [UMT3]
R50  100  [R0402]
R51  100  [R0402]
R52  100  [R0402]
R53  100  [R0402]
R54  49.9  [R0402]
R55  49.9  [R0402]
R56  1K  [R0402]
R57  22  [R0402]
R58  200  [R0402]
R59  1K  [R0402]
R60  2K  [R0402]
R61  1K/dnp  [R0402]
R62  10K/dnp  [R0402]
R63  1K  [R0402]
R64  1K  [R0402]
R65  1K  [R0402]
R66  1K  [R0402]
R67  10K  [R0402]
R68  49.9  [R0402]
R69  0  [R0402]
R70  2K  [R0402]
R71  0  [R0402]
R72  10K  [R0402]
R73  10K  [R0402]
R74  1K  [R0402]
R75  1K  [R0402]
R76  1K  [R0402]
R77  1K  [R0402]
R928  0/DNP  [R0402]
R929  0  [R0402]
R930  0  [R0402]
R931  0/DNP  [R0402]
R932  0  [R0402]
R933  0/DNP  [R0402]
R934  0  [R0402]
R935  0/DNP  [R0402]
R936  0  [R0402]
R937  0/DNP  [R0402]
SW1  DIP SWITCH 1POS  [DIP_SW1]
TP2  TEST POINT  [TP_SMD]
TP3  TEST POINT  [TP_SMD]
TP4  TEST POINT  [TP_SMD]
X1  ECS-3963-500-BN-TR  [4smd-5x3_2x1_3mm]
sheet 13.CN81XX CORE VDD
U1  CN8130-1500BG676-SCP-PR11-G  [BGA-676]  (sections A,B,C,D,E,F,G,H,I,J,K)
sheet 53.IO-EXPANDER
C848  0.1uF  [C0402]
C850  0.1uF  [C0402]
C885  0.1uF  [C0402]
C886  0.1uF  [C0402]
C910  0.1uF  [C0402]
C911  0.1uF  [C0402]
C912  0.1uF  [C0402]
R693  10K  [R0402]
R694  10K  [R0402]
R695  10K  [R0402]
R698  0  [R0402]
R702  10K  [R0402]
R703  10K  [R0402]
R809  0  [R0402]
R810  10K  [R0402]
R811  10K  [R0402]
R812  10K  [R0402]
R813  0  [R0402]
R814  0  [R0402]
R815  0  [R0402]
R816  0  [R0402]
R817  0  [R0402]
R818  0  [R0402]
R819  0  [R0402]
R820  0  [R0402]
R821  0  [R0402]
R822  0  [R0402]
R823  0  [R0402]
R824  0  [R0402]
R825  0  [R0402]
R826  0  [R0402]
R827  0  [R0402]
R828  0  [R0402]
R829  0  [R0402]
R830  0  [R0402]
R831  0  [R0402]
R832  0  [R0402]
R833  0  [R0402]
R834  0  [R0402]
R835  0  [R0402]
R836  0  [R0402]
R837  0  [R0402]
R838  0  [R0402]
R839  0  [R0402]
R840  0  [R0402]
R842  0  [R0402]
R843  0  [R0402]
R853  0  [R0402]
R907  0  [R0402]
U80  SX1509B  [QFN40P400X400X60-29N]
U89  SX1509B  [QFN40P400X400X60-29N]
U92  74LVC07A  [TSSOP14-P065]
U93  74LVC07A  [TSSOP14-P065]
U94  74LVC07A  [TSSOP14-P065]
sheet 54. SuperCap Back-Up
A5  Custom Board Spacer  [9774030243R]
C843  1000PF  [C1812]
C879  10uF  [C0603]
C880  10uF  [C0603]
C881  10uF  [C0603]
C882  10uF  [C0603]
J28  91601-306LF  [91601-306LF]
MH1  Mounting_Hole  [MTG370_800]
MH2  Mounting_Hole  [MTG370_800]
MH3  Mounting_Hole  [MTG370_800]
MH5  Mounting_Hole  [MTG370_800]
MH6  Mounting_Hole  [MTG370_800]
MH8  Mounting_Hole  [MTG370_800]
MH10  Mounting_Hole  [MTG370_800]
MH13  Mounting_Hole  [SMD-5MM]
R783  267K  [R0402]
R784  7.5K  [R0402]
R785  100K  [R0402]
R854  1M  [R0402]
R855  1M  [R0402]
TP72  TEST POINT  [TP_SMD]
TP73  TEST POINT  [TP_SMD]
U87  LTC4415IMSE  [MSOP16-050-0504LH]

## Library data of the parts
D1-D4 = LED_wp117: LED GREEN DIFFUSED 0603 SMD; Manufacturer: Lumex; Manufacturer Part Number: SML-LX0603GW-TR; Part Number: LTST-C190KGKT
D5 = LED_wp117: LED RED DIFFUSED 0603 SMD; Manufacturer: Lumex; Manufacturer Part Number: SML-LX0603IW-TR; Part Number: LTST-C190KRKT
J33 = 4_HEADER: CONN HEADER 4POS 2.54MM SMT; Manufacturer: Wurth electronics inc.; Manufacturer Part Number: 61000418221
MH13 MH16 = Mounting_Hole_0: Section: SG1000
Q1-Q6 = MOSFET_N_GDS: MOSFET N-CH 30V 300MA UMT3; Manufacturer: Rohm; Manufacturer Part Number: RJU003N03T106; PART_NUMBER: RJU003N03T106
R1 = RESISTOR_1: RES SMD 100K OHM 5% 1/16W 0402; Manufacturer: VISHAY DALE; Manufacturer Part Number: CRCW0402100KJNED; Tolerance: ±5%; Wattage: 1/16W
R2 R69 R71 R911 R915 R928-R937 = RES_0: RES SMD 0.0OHM JUMPER 1/16W 0402; MFG: Panasonic; MFG_PN: ERJ-2GE0R00X; Manufacturer: VISHAY DALE; Manufacturer Part Number: CRCW04020000Z0ED; PART_NUMBER: PAC_RES_02050
R3-R7 R58 = RESISTOR_1: RES SMD 200 OHM 1% 1/16W 0402; Manufacturer: VISHAY DALE; Manufacturer Part Number: CRCW0402200RFKED; Tolerance: 1%; Wattage: 1/16W
R8-R12 = R: RES 10 OHM 1/10W 1% 0402 SMD; MFG: Panasonic; MFG_PN: ERJ-2RKF10R0X; Manufacturer: Panasonic; Manufacturer Part Number: ERJ-2RKF10R0X; PART_NUMBER: ERJ-2RKF10R0X; Tolerance: 1%
U100 = SP3002-04JTG
C1 C2 C4 C8 C9 C14 C17 C18 C31 C32 C34 C53 C54 C56 C57 = cap_0402_1uF_10V_10%_X5R_smd
C3 C5 C6 C10-C12 C15 C16 C20-C24 C37-C52 C848 C850 C885 C886 C910-C912 = cap_0402_0.1uF_16V_10%_X7R: CAP CER 0.1UF 25V 10% X7R 0402; Manufacturer: MURATA; Manufacturer Part Number: GRM155R71C104KA88D; Voltage: 25V
C7 = cap_0805_10uF_16V_10%_X5R: CAP CER 10UF 16V X5R 0603; MFG: MURATA; MFG_PN: GRM188R60J106ME47D
C13 = cap_0805_10uF_16V_10%_X5R: MFG: MURATA; MFG_PN: GRM21BR61C106KE15K
C19 = cap_0805_4.7uF_10V_10%_X5R: CAP 0603 CER 4.7uF 10V 10% X5R; MFG: TDK; MFG_PN: C1608X7S1A475K080AC
C25 = cap_0805_10uF_16V_10%_X5R: CAP CER 10UF 6.3V X5R 0603; MFG: MURATA; MFG_PN: GRM21BR61C106KE15K; Voltage: 6.3V
C26 C27 = cap_0603_22uF_6V3_10%_X5R: MFG: Murata; MFG_PN: GRM187R60J226ME15D
C28 = cap_1206_100uF_10V_20%_X5R_smd: CAP CER 100UF 6.3V 20% X7U 1210; MFG: Murata; MFG_PN: GRM32EE70J107ME15L; Manufacturer: MURATA; Manufacturer Part Number: GRM32ER60J107ME20K; Voltage: 6.3V
C29 = cap_tant_330uF_6V3_20%_0: Manufacturer: Panasonic; Manufacturer Part Number: 6TPF330M9L
C30 C33 C55 = cap_0402_1uF_10V_10%_X5R_smd: CAP CER 1UF 10V 10% X7S 0402; MFG_PN: GCM155C71A105KE38D; Manufacturer: TDK; Manufacturer Part Number: C1005X7S1A105K050BC
C35 = cap_0402_0.01uF_16V_10%_X7R: CAP CER 10000PF 25V X7R 0402 10%; Manufacturer: Murata; Manufacturer Part Number: GRM155R71E103KA01D; Voltage: 25V
C36 C58 C59 C73 = cap_0402_0.01uF_16V_10%_X7R: CAP  0402 CER 0.01uF 16V 10%  X7R; Manufacturer: Murata; Manufacturer Part Number: GRM155R71C103KA01J; Voltage: 16V
R13-R15 R18 R23-R27 R57 = RESISTOR_1: RES SMD 22 OHM 1% 1/16W 0402; MFG: VISHAY DALE; MFG_PN: CRCW040222R0FKED; Manufacturer: VISHAY DALE; Manufacturer Part Number: CRCW040222R0FKED; Tolerance: ±1%; Wattage: 1/16W
R16 = RESISTOR_1: RES SMD 60.4 OHM 1% 1/16W 0402; Manufacturer: YAGEO; Manufacturer Part Number: RC0402FR-0760R4L; Tolerance: 1%; Wattage: 1/16W
R17 = RESISTOR_1: RES SMD 240 OHM 1% 1/16W 0402; Manufacturer: VISHAY DALE; Manufacturer Part Number: CRCW0402240RFKED; Tolerance: 1%; Wattage: 1/16W
R19 R20 = res_0402_22R6_0.063W_1%_SMD: Manufacturer: Vishay Dale; Manufacturer Part Number: CRCW040222R6FKED
R21 = res_0402_10K0_0.063W_1%_smd
R22 = res_0402_1K0_0.063W_1%_smd: RES SMD 1K OHM 1% 1/10W 0402; MFG: Panasonic; MFG_PN: ERJ-2RKF1001X; Manufacturer: Panasonic; Manufacturer Part Number: ERJ-2RKF1001X
R28 = RESISTOR_1: RES SMD 4.7K OHM 5% 1/16W 0402; Manufacturer: Panasonic; Manufacturer Part Number: ERJ-2GEJ472X; Tolerance: 5%; Wattage: 1/16W
R29 R30 = res_0402_2K0_0.063W_1%_smd: RES SMD 2K OHM 5% 1/10W 0402; MFG: Panasonic; MFG_PN: ERJ-2GEJ202X; Manufacturer: Panasonic; Manufacturer Part Number: ERJ-2GEJ202X; Tolerance: ?%
R31-R33 = res_0402_220R0_0.063W_1%_smd: Manufacturer: VISHAY DALE; Manufacturer Part Number: CRCW0402220RFKED
U2 = DDR4_260PIN_SO-DIMM_0: DDR4 SODIMM 260P 5.2H; Manufacturer: TE Connectivity AMP Connectors; Manufacturer Part Number: 2309407-1
U3 = IC_LVL_SHFTR_TXS0102DCUR: Manufacturer: Texas Instruments
C71 C72 = CAP_NONPOL: CAP CER 0.1UF 25V 10% X7R 0402; MFG: Murata; MFG_PN: GRM155R71C104KA88D; Manufacturer: MURATA; Manufacturer Part Number: GRM155R71C104KA88D; Tolerance: ±10%; Voltage: 25V
D6 = LED: LED GREEN DIFFUSED 0603 SMD; Manufacturer: Lumex; Manufacturer Part Number: SML-LX0603GW-TR
FB1 = fer_120_1.5A_BLM15EG121SN1D_sm: Manufacturer: MURATA; Manufacturer Part Number: BLM15EG121SN1D
J1 = 2_PIN_HEADER_0: 2 Positions Header, Unshrouded, Breakaway Connector 0.100" (2.54mm) Through Hole Gold; Manufacturer: TE Connectivity; Manufacturer Part Number: 5-146280-2
J2 = eJTAG_Header_6: CONN HDR 1.27MM SMD AU 20POS; Manufacturer: Harwin Inc
R50-R53 = RESISTOR_1: RES SMD 100 OHM 1% 1/16W 0402; Manufacturer: VISHAY DALE; Manufacturer Part Number: CRCW0402100RFKED; Tolerance: 1%; Wattage: 1/16W
R54 R55 R68 = RESISTOR_1: RES SMD 49.9 OHM 1% 1/10W 0402; Manufacturer: Panasonic; Manufacturer Part Number: ERJ-2RKF49R9X; Tolerance: 1%; Wattage: 1/16W
R56 = res_0402_1K0_0.063W_1%_smd: RES SMD 1K OHM 5% 1/16W 0402; Manufacturer: VISHAY DALE; Manufacturer Part Number: CRCW04021K00JNED; Tolerance: ?%
R59 R61 R63-R65 R74-R77 = RESISTOR_1: RES SMD 1K OHM 5% 1/16W 0402; MFG: VISHAY DALE; MFG_PN: CRCW04021K00JNED; Manufacturer: VISHAY DALE; Manufacturer Part Number: CRCW04021K00JNED; Tolerance: ±5%; Wattage: 1/10W
R60 R70 = RESISTOR_1: RES SMD 2K OHM 5% 1/10W 0402; MFG: Panasonic; MFG_PN: ERJ-2GEJ202X; Manufacturer: Panasonic; Manufacturer Part Number: ERJ-2GEJ202X; Tolerance: ±5%; Wattage: 1/16W
R62 R67 R72 R73 = RESISTOR_1: RES SMD 10K OHM 5% 1/16W 0402; MFG: VISHAY DALE; MFG_PN: CRCW040210K0JNED; Manufacturer: VISHAY DALE; Manufacturer Part Number: CRCW040210K0JNED; Tolerance: ±5%; Wattage: 1/16W
R66 = RESISTOR_1: RES SMD 1K OHM 5% 1/16W 0402; MFG: VISHAY DALE; MFG_PN: CRCW04021K00JNED; Manufacturer: VISHAY DALE; Manufacturer Part Number: CRCW04021K00JNED; Tolerance: 5%; Wattage: 1/10W
SW1 = DIP_SWITCH_1POS: SWITCH SLIDE DIP SPST 25MA 24V; Manufacturer: C&K Components; Manufacturer Part Number: TDA01H0SB1R
TP2-TP4 TP72 TP73 = TEST_POINT
X1 = CB3LV-3I-50M0000-T: OSC XO 50.000MHZ HCMOS TTL SMD; MFG: Abracon; MFG_PN: ASFL1-50.000MHZ-EC-T; Manufacturer: ECS inc.
U1 = CN81XX_List_V0_3.60: Manufacturer: CAVIUM
R693-R695 R810 R811 = R_1: RES SMD 10K OHM 5% 1/16W 0402; Manufacturer: VISHAY DALE; Manufacturer Part Number: CRCW040210K0JNED; Part Number: ERJ-2GEJ103X; TOLERANCE: 5%; WATTAGE: 1/16W
R698 R809 = RES_22_OHM_1_10W_5%_0402_SMD_0: RES SMD 0.0OHM JUMPER 1/16W 0402; Manufacturer: VISHAY DALE; Manufacturer Part Number: CRCW04020000Z0ED; Part Number: ERJ-2GE0R00X; TOLERANCE: 1%; WATTAGE: 1/10W
R702 R703 = RESISTOR_1: RES SMD 10K OHM 5% 1/16W 0402; Manufacturer: VISHAY DALE; Manufacturer Part Number: CRCW040210K0JNED; Tolerance: ±5%; Wattage: 1/16W
R812 = R_1: RES SMD 10K OHM 5% 1/16W  0402; Manufacturer: VISHAY DALE; Manufacturer Part Number: CRCW040210K0JNED; Part Number: ERJ-2GEJ103X; TOLERANCE: 5%; WATTAGE: 1/10W
R813-R840 R842 R843 R853 R907 = RES_1.0_OHM_1_16W_0402_SMD: RES SMD 0.0OHM JUMPER 1/16W 0402; MATERIAL: ?; Manufacturer: VISHAY DALE; Manufacturer Part Number: CRCW04020000Z0ED; Part Number: ERJ-2GE0R00X; TOLERANCE: ?; Wattage: 1/10W
U80 U89 = SX1509B_1: IC GPIO EXPANDER I2C 16CH 28QFN; Manufacturer: Semtech; Manufacturer Part Number: SX1509BIULTRT; Part Number: SX1509BIULTRT
U92-U94 = 74LVC07A
A5 = 4-881545-2: ROUND STANDOFF M2 STEEL 3MM; Manufacturer: Wurth Electronics Inc
C843 = CAP_CER_0.1UF_10V_10%_X5R_0402: CAP CER 1000PF 3KV X7R 1812; MATERIAL: X7R; Manufacturer: KEMET; Manufacturer Part Number: C1812C102KHRACTU; PART_NUMBER: 0.1UF; Part Number: 202R18W102KV4E; TOLERANCE: 10%; VOLTAGE: 3KV
C879-C882 = CAP_NONPOL_0: CAP CER 10UF 6.3V X5R 0603; Manufacturer: MURATA; Manufacturer Part Number: GRM188R60J106KE47D; Tolerance: ±10%; Voltage: 6.3V
J28 = 91601-306LF
MH1-MH3 MH5 MH6 MH8 MH10 = Mounting_Hole_0
R783 = RES_0402: RES SMD 267K OHM 1% 1/16W 0402; Manufacturer: VISHAY DALE; Manufacturer Part Number: CRCW0402267KFKED; Tolerance: 1%
R784 = res_0402_2K0_0.063W_1%_smd: RES SMD 7.5K OHM 1% 1/16W 0402; MFG: Panasonic; MFG_PN: ERJ-2GEJ202X; Manufacturer: VISHAY DALE; Manufacturer Part Number: CRCW04027K50FKED; Tolerance: ?%
R785 = RESISTOR_1: RES SMD 100K OHM 1% 1/16W 0402; Manufacturer: VISHAY DALE; Manufacturer Part Number: CRCW0402100KFKED; Tolerance: 1%; Wattage: 1/16W
R854 R855 = RESISTOR_2: RES SMD 1M OHM 1% 1/16W 0402; Manufacturer: VISHAY DALE; Manufacturer Part Number: CRCW04021M00FKED; Part Number: RC0402FR-071ML; TOLERANCE: 1%; WATTAGE: 1/16W
U87 = LTC4415IMSE

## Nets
GND: C1.2 C2.2 C3.2 C4.2 C5.2 C6.2 C7.1 C8.2 C9.2 C10.2 C11.2 C12.2 C13.1 C14.2 C15.2 C16.2 C17.2 C18.2 C19.1 C20.2 C21.2 C22.2 C23.2 C24.2 C25.1 C26.1 C27.1 C28.2 C29.2N C30.2 C31.2 C32.2 C33.2 C34.2 C35.1 C36.1 C37.2 C38.2 C39.2 C40.2 C41.2 C42.2 C43.2 C44.2 C45.2 C46.2 C47.2 C48.2 C49.2 C50.2 C51.2 C52.2 C53.2 C54.2 C55.2 C56.2 C57.2 C58.1 C59.1 C73.1 C843.1(A[0]) C848.2 C850.2 C879.2 C880.2 C881.2 C882.2 C885.2 C886.2 C910.2 C911.2 C912.2 J2.4 J2.6 J2.8 J2.10 J2.12 J2.14 J2.16 J2.18 J2.20 J28.2 J28.6 J33.4 MH3.1 MH5.1 MH6.1 MH8.1 Q1.S Q2.S Q3.S Q4.S Q5.S Q6.S R17.1 R20.1 R31.2 R32.2 R33.2 R52.1 R53.1 R54.1 R55.1 R60.1 R68.1 R70.1 R74.1 R75.1 R76.1 R77.1 R702.1 R703.1 R785.1 R812.2(B[0]) SW1.16(B0) U2.1(VSS) U2.2(VSS) U2.5(VSS) U2.6(VSS) U2.9(VSS) U2.10(VSS) U2.14(VSS) U2.15(VSS) U2.18(VSS) U2.19(VSS) U2.22(VSS) U2.23(VSS) U2.26(VSS) U2.27(VSS) U2.30(VSS) U2.31(VSS) U2.35(VSS) U2.36(VSS) U2.39(VSS) U2.40(VSS) U2.43(VSS) U2.44(VSS) U2.47(VSS) U2.48(VSS) U2.51(VSS) U2.52(VSS) U2.56(VSS) U2.57(VSS) U2.60(VSS) U2.61(VSS) U2.64(VSS) U2.65(VSS) U2.68(VSS) U2.69(VSS) U2.72(VSS) U2.73(VSS) U2.77(VSS) U2.78(VSS) U2.81(VSS) U2.82(VSS) U2.85(VSS) U2.86(VSS) U2.89(VSS) U2.90(VSS) U2.93(VSS) U2.94(VSS) U2.98(VSS) U2.99(VSS) U2.102(VSS) U2.103(VSS) U2.106(VSS) U2.107(VSS) U2.167(VSS) U2.168(VSS) U2.171(VSS) U2.172(VSS) U2.175(VSS) U2.176(VSS) U2.180(VSS) U2.181(VSS) U2.184(VSS) U2.185(VSS) U2.188(VSS) U2.189(VSS) U2.192(VSS) U2.193(VSS) U2.196(VSS) U2.197(VSS) U2.201(VSS) U2.202(VSS) U2.205(VSS) U2.206(VSS) U2.209(VSS) U2.210(VSS) U2.213(VSS) U2.214(VSS) U2.217(VSS) U2.218(VSS) U2.222(VSS) U2.223(VSS) U2.226(VSS) U2.227(VSS) U2.230(VSS) U2.231(VSS) U2.234(VSS) U2.235(VSS) U2.238(VSS) U2.239(VSS) U2.243(VSS) U2.244(VSS) U2.247(VSS) U2.248(VSS) U2.251(VSS) U2.252(VSS) U3.2(GND) U80.3(GND1) U80.17(GND2) U80.29(TP) U87.4(CLIM1) U87.5(CLIM2) U87.17(EGND) U89.3(GND1) U89.17(GND2) U89.29(TP) U92.7(GND) U93.7(GND) U94.7(GND) U100.2(GND) X1.2(GND) ; also on sheet 13 14 15 16 17 18 19 20 21 22 23 24 25 26 27 28 29 30 31 32 33 34 35 36 37 38 39 40 41 42 43 44 45 46 47 48 49 50 51 52 53 54
V1P2_DDR: C22.1 C23.1 C24.1 C25.2 C26.2 C27.2 C28.1 C29.1P C30.1 C31.1 C32.1 C33.1 C34.1 C35.2 C36.2 C37.1 C38.1 C39.1 C40.1 C41.1 C42.1 C43.1 C44.1 C45.1 C46.1 C47.1 C48.1 C49.1 C50.1 C51.1 C52.1 C53.1 C54.1 C55.1 C56.1 C57.1 C58.2 C59.2 R13.2 R14.2 R15.2 R16.1 R18.2 R19.1 R22.1 R23.2 R24.2 R25.2 R26.2 R27.2 R50.2 R51.2 U2.111(VDD) U2.112(VDD) U2.117(VDD) U2.118(VDD) U2.123(VDD) U2.124(VDD) U2.129(VDD) U2.130(VDD) U2.135(VDD) U2.136(VDD) U2.141(VDD) U2.142(VDD) U2.147(VDD) U2.148(VDD) U2.153(VDD) U2.154(VDD) U2.159(VDD) U2.160(VDD) U2.163(VDD) ; also on sheet 13 16 30
V2P5: C1.1 C2.1 C3.1 C4.1 C5.1 C6.1 C7.2 C21.1 R21.1 R28.2 R29.2 R30.2 U2.255(VDDSPD) U2.257(VPP) U2.259(VPP) U3.3(VCCA) ; also on sheet 31 50 51 53
V3P3: C20.1 FB1.2 J2.1 R1.2 R3.2 R4.2 R5.2 R6.2 R7.2 R58.2 R61.2 R62.1 R63.2 R64.2 R65.2 R66.2 R67.1 R72.2 R73.2 U3.7(VCCB) ; also on sheet 14 17 18 22 24 25 26 27 29 30 31 32 33 34 35 43 45 49 51 53 54
V3P3_TIVA_CM: C881.1 C882.1 R854.1 R855.1 U87.9(OUT2_1) U87.10(OUT2_2) U87.15(OUT1_1) U87.16(OUT1_2) ; also on sheet 38
V3P3_TIVA_LT: C848.1 C850.1 C879.1 C885.1 C886.1 C910.1 C911.1 C912.1 J28.1 R693.1(A[0]) R694.1(A[0]) R695.1(A[0]) R783.1 R810.1(A[0]) R811.1(A[0]) U80.4(VCC1) U80.12(VDDM) U80.18(VCC2) U87.1(IN1) U87.2(IN1) U89.4(VCC1) U89.12(VDDM) U89.18(VCC2) U92.14(VCC) U93.14(VCC) U94.14(VCC) ; also on sheet 19 20 21 28 29 31 37 38 39 40 42 43 44 46 47 52 54
VDD_OSC_PLL: C73.2 FB1.1 R56.2 X1.4(VCC)
2G_SIM_PRESENCE: R813.1(A[0]) ; also on sheet 42
2GMODULE_POWEROFF: R703.2 R814.1(A[0]) ; also on sheet 42
BOOT_METHOD_GPIO_0: R836.1(A[0]) U1.T6(BOOT_METHOD_0/GPIO_0) ; also on sheet 17
BOOT_METHOD_GPIO_1: R837.1(A[0]) U1.T7(BOOT_METHOD_1/GPIO_1) ; also on sheet 17
BOOT_METHOD_GPIO_2: R838.1(A[0]) U1.U4(BOOT_METHOD_2/GPIO_2) ; also on sheet 17
BOOT_METHOD_GPIO_3: R839.1(A[0]) U1.U5(BOOT_METHOD_3/GPIO_3) ; also on sheet 17
C_OCT_DAP_TRST_L: J2.3 R62.2 R77.2 R932.2
C_OCT_JTAG_TCK: J2.9 R65.1 R936.2
C_OCT_JTAG_TDI: J2.5 R63.1 R929.2
C_OCT_JTAG_TDO: J2.13 R66.1 R930.2
C_OCT_JTAG_TMS: J2.7 R64.1 R934.2
CFG_IOEXP_TIVA_INT: R809.2(B[0]) ; also on sheet 37
CHASIS_GND: C843.2(B[0]) MH1.1 MH2.1 MH10.1 ; also on sheet 21 25 28
CHIP_RESET_OUT_L: TP2.1 U1.P8(CHIP_RESET_OUT_L)
CORE_OSC_R: R57.2 X1.3(OUT)
DDR0_A0: U1.G16(DDR_A<0>) U2.144(A0)
DDR0_A1: U1.F12(DDR_A<1>) U2.133(A1)
DDR0_A2: U1.G12(DDR_A<2>) U2.132(A2)
DDR0_A3: U1.D12(DDR_A<3>) U2.131(A3)
DDR0_A4: U1.E12(DDR_A<4>) U2.128(A4)
DDR0_A5: U1.E11(DDR_A<5>) U2.126(A5)
DDR0_A6: U1.D11(DDR_A<6>) U2.127(A6)
DDR0_A7: U1.E10(DDR_A<7>) U2.122(A7)
DDR0_A8: U1.G11(DDR_A<8>) U2.125(A8)
DDR0_A9: U1.F10(DDR_A<9>) U2.121(A9)
DDR0_A10_AP: U1.B15(DDR_A<10>) U2.146(A10/AP)
DDR0_A11: U1.D9(DDR_A<11>) U2.120(A11)
DDR0_A12_BC#: U1.G10(DDR_A<12>) U2.119(A12)
DDR0_A13: U1.B17(DDR_A<13>) U2.158(A13)
DDR0_A14_BG0: U1.F9(DDR_A<14>_BG0) U2.115(BG0)
DDR0_A15_BG1: U1.D8(DDR_A<15>_BG1) U2.113(BG1)
DDR0_ACT#: U1.D7(DDR_RSVD_ACT_L) U2.114(ACT_N)
DDR0_ALERT#: R22.2 U2.116(ALERT_N)
DDR0_BA0: U1.E16(DDR_BA0) U2.150(BA0)
DDR0_BA1: U1.F16(DDR_BA1) U2.145(BA1)
DDR0_BA2_TEN: U1.E9(DDR_BA2_TEN)
DDR0_CAS#_A15: U1.A16(DDR_CAS_L_A<15>) U2.156(A15/CAS_N)
DDR0_CK0_N: U1.F14(DDR_CK_0_N) U2.139(CK0_C)
DDR0_CK0_P: U1.G14(DDR_CK_0_P) U2.137(CK0_T)
DDR0_CK1_N: U1.D14(DDR_CK_1_N) U2.140(CK1_C)
DDR0_CK1_P: U1.E14(DDR_CK_1_P) U2.138(CK1_T)
DDR0_CKE0: U1.F8(DDR_CKE0) U2.109(CKE0)
DDR0_CKE1: U1.E7(DDR_CKE1) U2.110(CKE1)
DDR0_COMP_DN: R16.2 U1.K7(DDR_COMP_DN)
DDR0_COMP_UP: R17.2 U1.H8(DDR_COMP_UP)
DDR0_CS0#: U1.C16(DDR_CS0_L) U2.149(CS0_N)
DDR0_CS1#: U1.C17(DDR_CS1_L) U2.157(CS1_N)
DDR0_DM0: R14.1 U2.12(DM0_N/DBI0_N/NC)
DDR0_DM1: R13.1 U2.33(DM1_N/DBI1_N/NC)
DDR0_DM2: R15.1 U2.54(DM2_N/DBI2_N/NC)
DDR0_DM3: R18.1 U2.75(DM3_N/DBI3_N/NC)
DDR0_DM4: R23.1 U2.178(DM4_N/DBI4_N/NC)
DDR0_DM5: R24.1 U2.199(DM5_N/DBI5_N/NC)
DDR0_DM6: R26.1 U2.220(DM6_N/DBI6_N/NC)
DDR0_DM7: R27.1 U2.241(DM7_N/DBI7_N/NC)
DDR0_DM8: R25.1 U2.96(DM8_N/DBI8_N/NC)
DDR0_DQ0: U1.L1(DDR_DQ<0>) U2.8(DQ0)
DDR0_DQ1: U1.K2(DDR_DQ<1>) U2.7(DQ1)
DDR0_DQ2: U1.G1(DDR_DQ<2>) U2.20(DQ2)
DDR0_DQ3: U1.G2(DDR_DQ<3>) U2.21(DQ3)
DDR0_DQ4: U1.M1(DDR_DQ<4>) U2.4(DQ4)
DDR0_DQ5: U1.L2(DDR_DQ<5>) U2.3(DQ5)
DDR0_DQ6: U1.H3(DDR_DQ<6>) U2.16(DQ6)
DDR0_DQ7: U1.H2(DDR_DQ<7>) U2.17(DQ7)
DDR0_DQ8: U1.K4(DDR_DQ<8>) U2.28(DQ8)
DDR0_DQ9: U1.K5(DDR_DQ<9>) U2.29(DQ9)
DDR0_DQ10: U1.G4(DDR_DQ<10>) U2.41(DQ10)
DDR0_DQ11: U1.G5(DDR_DQ<11>) U2.42(DQ11)
DDR0_DQ12: U1.L5(DDR_DQ<12>) U2.24(DQ12)
DDR0_DQ13: U1.L4(DDR_DQ<13>) U2.25(DQ13)
DDR0_DQ14: U1.H5(DDR_DQ<14>) U2.38(DQ14)
DDR0_DQ15: U1.H6(DDR_DQ<15>) U2.37(DQ15)
DDR0_DQ16: U1.B3(DDR_DQ<16>) U2.50(DQ16)
DDR0_DQ17: U1.A4(DDR_DQ<17>) U2.49(DQ17)
DDR0_DQ18: U1.A7(DDR_DQ<18>) U2.62(DQ18)
DDR0_DQ19: U1.B7(DDR_DQ<19>) U2.63(DQ19)
DDR0_DQ20: U1.A2(DDR_DQ<20>) U2.46(DQ20)
DDR0_DQ21: U1.A3(DDR_DQ<21>) U2.45(DQ21)
DDR0_DQ22: U1.B6(DDR_DQ<22>) U2.58(DQ22)
DDR0_DQ23: U1.A6(DDR_DQ<23>) U2.59(DQ23)
DDR0_DQ24: U1.D1(DDR_DQ<24>) U2.70(DQ24)
DDR0_DQ25: U1.D2(DDR_DQ<25>) U2.71(DQ25)
DDR0_DQ26: U1.D4(DDR_DQ<26>) U2.83(DQ26)
DDR0_DQ27: U1.D5(DDR_DQ<27>) U2.84(DQ27)
DDR0_DQ28: U1.E1(DDR_DQ<28>) U2.66(DQ28)
DDR0_DQ29: U1.E2(DDR_DQ<29>) U2.67(DQ29)
DDR0_DQ30: U1.E4(DDR_DQ<30>) U2.79(DQ30)
DDR0_DQ31: U1.E5(DDR_DQ<31>) U2.80(DQ31)
DDR0_DQ32: U1.E19(DDR_DQ<32>) U2.174(DQ32)
DDR0_DQ33: U1.D19(DDR_DQ<33>) U2.173(DQ33)
DDR0_DQ34: U1.D22(DDR_DQ<34>) U2.187(DQ34)
DDR0_DQ35: U1.E22(DDR_DQ<35>) U2.186(DQ35)
DDR0_DQ36: U1.E18(DDR_DQ<36>) U2.170(DQ36)
DDR0_DQ37: U1.D18(DDR_DQ<37>) U2.169(DQ37)
DDR0_DQ38: U1.D21(DDR_DQ<38>) U2.183(DQ38)
DDR0_DQ39: U1.E21(DDR_DQ<39>) U2.182(DQ39)
DDR0_DQ40: U1.A19(DDR_DQ<40>) U2.195(DQ40)
DDR0_DQ41: U1.C20(DDR_DQ<41>) U2.194(DQ41)
DDR0_DQ42: U1.B22(DDR_DQ<42>) U2.207(DQ42)
DDR0_DQ43: U1.A23(DDR_DQ<43>) U2.208(DQ43)
DDR0_DQ44: U1.A18(DDR_DQ<44>) U2.191(DQ44)
DDR0_DQ45: U1.B19(DDR_DQ<45>) U2.190(DQ45)
DDR0_DQ46: U1.B21(DDR_DQ<46>) U2.203(DQ46)
DDR0_DQ47: U1.A22(DDR_DQ<47>) U2.204(DQ47)
DDR0_DQ48: U1.F24(DDR_DQ<48>) U2.216(DQ48)
DDR0_DQ49: U1.F25(DDR_DQ<49>) U2.215(DQ49)
DDR0_DQ50: U1.H23(DDR_DQ<50>) U2.228(DQ50)
DDR0_DQ51: U1.H22(DDR_DQ<51>) U2.229(DQ51)
DDR0_DQ52: U1.G22(DDR_DQ<52>) U2.211(DQ52)
DDR0_DQ53: U1.F23(DDR_DQ<53>) U2.212(DQ53)
DDR0_DQ54: U1.G21(DDR_DQ<54>) U2.224(DQ54)
DDR0_DQ55: U1.H24(DDR_DQ<55>) U2.225(DQ55)
DDR0_DQ56: U1.C24(DDR_DQ<56>) U2.237(DQ56)
DDR0_DQ57: U1.B25(DDR_DQ<57>) U2.236(DQ57)
DDR0_DQ58: U1.D25(DDR_DQ<58>) U2.249(DQ58)
DDR0_DQ59: U1.E26(DDR_DQ<59>) U2.250(DQ59)
DDR0_DQ60: U1.B24(DDR_DQ<60>) U2.232(DQ60)
DDR0_DQ61: U1.A25(DDR_DQ<61>) U2.233(DQ61)
DDR0_DQ62: U1.D24(DDR_DQ<62>) U2.245(DQ62)
DDR0_DQ63: U1.D26(DDR_DQ<63>) U2.246(DQ63)
DDR0_DQS0_N: U1.J2(DDR_DQS_0_N) U2.11(DQS0_C)
DDR0_DQS0_P: U1.J1(DDR_DQS_0_P) U2.13(DQS0_T)
DDR0_DQS1_N: U1.J4(DDR_DQS_1_N) U2.32(DQS1_C)
DDR0_DQS1_P: U1.J5(DDR_DQS_1_P) U2.34(DQS1_T)
DDR0_DQS2_N: U1.B4(DDR_DQS_2_N) U2.53(DQS2_C)
DDR0_DQS2_P: U1.B5(DDR_DQS_2_P) U2.55(DQS2_T)
DDR0_DQS3_N: U1.E3(DDR_DQS_3_N) U2.74(DQS3_C)
DDR0_DQS3_P: U1.D3(DDR_DQS_3_P) U2.76(DQS3_T)
DDR0_DQS4_N: U1.E20(DDR_DQS_4_N) U2.177(DQS4_C)
DDR0_DQS4_P: U1.F20(DDR_DQS_4_P) U2.179(DQS4_T)
DDR0_DQS5_N: U1.A20(DDR_DQS_5_N) U2.198(DQS5_C)
DDR0_DQS5_P: U1.B20(DDR_DQS_5_P) U2.200(DQS5_T)
DDR0_DQS6_N: U1.G23(DDR_DQS_6_N) U2.219(DQS6_C)
DDR0_DQS6_P: U1.G24(DDR_DQS_6_P) U2.221(DQS6_T)
DDR0_DQS7_N: U1.B26(DDR_DQS_7_N) U2.240(DQS7_C)
DDR0_DQS7_P: U1.C26(DDR_DQS_7_P) U2.242(DQS7_T)
DDR0_DQS8_N: U1.B10(DDR_DQS_8_N) U2.95(DQS8_C)
DDR0_DQS8_P: U1.B11(DDR_DQS_8_P) U2.97(DQS8_T)
DDR0_ECC1: U1.C10(DDR_CB<0>) U2.92(CB0/NC)
DDR0_ECC2: U1.A10(DDR_CB<1>) U2.91(CB1/NC)
DDR0_ECC3: U1.A13(DDR_CB<2>) U2.101(CB2/NC)
DDR0_ECC4: U1.B13(DDR_CB<3>) U2.105(CB3/NC)
DDR0_ECC5: U1.B9(DDR_CB<4>) U2.88(CB4/NC)
DDR0_ECC6: U1.A9(DDR_CB<5>) U2.87(CB5/NC)
DDR0_ECC7: U1.A12(DDR_CB<6>) U2.100(CB6/NC)
DDR0_ECC8: U1.B12(DDR_CB<7>) U2.104(CB7/NC)
DDR0_ENENT#: R21.2 U2.134(EVENT_N)
DDR0_ODT0: U1.D16(DDR_ODT_0) U2.155(ODT0)
DDR0_ODT1: U1.F17(DDR_ODT_1) U2.161(ODT1)
DDR0_PARITY: R19.2 R20.2 U2.143(PARITY)
DDR0_RAS#_A16: U1.A15(DDR_RAS_L_A<16>) U2.152(A16/RAS_N)
DDR0_RESET#: U1.F7(DDR_RESET_L) U2.108(RESET_N)
DDR0_SA0: R31.1 U2.256(SA0)
DDR0_SA1: R32.1 U2.260(SA1)
DDR0_SA2: R33.1 U2.166(SA2)
DDR0_SCL: R30.1 U2.253(SCL) U3.5(A1)
DDR0_SDA: R29.1 U2.254(SDA) U3.4(A2)
DDR0_WE#_A14: U1.B16(DDR_WE_L_A<14>) U2.151(A14/WE_N)
DDR_100M_REFCLK_C_N: C72.2 R51.1 R52.2 U1.G26(DDR_ALT_REF_CLK_N)
DDR_100M_REFCLK_C_P: C71.2 R50.1 R53.2 U1.H26(DDR_ALT_REF_CLK_P)
DDR_100M_REFCLK_N: C72.1 ; also on sheet 35
DDR_100M_REFCLK_P: C71.1 ; also on sheet 35
DLMC_REF_CLK1_N: U1.AF20(DLMC_REF_CLK1_N) ; also on sheet 34
DLMC_REF_CLK1_P: U1.AE20(DLMC_REF_CLK1_P) ; also on sheet 34
EJTAG_DINT: J2.15 R67.2 R71.1
EMMC_BOOT_ISOLATE: U1.V3(EMMC_RESET/GPIO_8) ; also on sheet 49
ENABLE_STAGE5: R11.1 ; also on sheet 32 33
ETHSW_TEMP_EVENT: R819.1(A[0]) ; also on sheet 46
ETHSW_TIVA_IBA: R843.1(A[0]) ; also on sheet 19
ETHSW_TIVA_PME_N: R842.1(A[0]) ; also on sheet 19
GPIO10: U1.V5(GPIO_10) ; also on sheet 17
GPIO11_FAIL_BLINK: R12.1 U1.V6(GPIO_11)
GPIO12: U1.V7(GPIO_12) ; also on sheet 17
GPIO37_MEM_RST_L: U1.AC1(PBUS_AD_22/GPIO_38) ; also on sheet 32
IDT_1588_1PPS_IN: R911.1 ; also on sheet 45
IDT_1588_1PPS_OUT: U1.AE4(PBUS_AD_31/GPIO_47) ; also on sheet 45
IDT_1588_CLK_OUT: U1.AE3(PBUS_AD_30/GPIO_46) ; also on sheet 45
IOEXP_ID_EEPROM_WP: R825.1(A[0]) ; also on sheet 41
IOEXP_INVEN_EEPROM_WP: R824.1(A[0]) ; also on sheet 41
IOEXP_TIVA_INT: R698.2(B[0]) ; also on sheet 37
LED_TEMP_EVENT: R820.1(A[0]) ; also on sheet 46
LT4415_EN: R783.2 R784.2 U87.3(EN1)
LT4415_EN2n: R784.1 R785.2 U87.6(~{EN2})
MANUAL_RST_L: R71.2 ; also on sheet 32
MPCIE0_WAKE#: U1.AA3(PBUS_CE_1_L/GPIO_27) ; also on sheet 26
mPCIE1_RST_L: U1.AA1(PBUS_ALE_3/GPIO_25) ; also on sheet 27
MPCIE1_WAKE#: U1.AA4(PBUS_OE_L/GPIO_28) ; also on sheet 27
OCT_DAP_TRST_L: R932.1 R933.1 U1.N4(JTG_DAP_TRST_L)
OCT_DC_OK: U1.AB14(PLL_DC_OK) ; also on sheet 32 37
OCT_JTAG_TCK: R936.1 R937.1 U1.P2(JTG_TCK)
OCT_JTAG_TDI: R928.1 R929.1 U1.P1(JTG_TDI)
OCT_JTAG_TDO: R930.1 R931.1 U1.P3(JTG_TDO)
OCT_JTAG_TMS: R934.1 R935.1 U1.N2(JTG_TMS)
OCT_JTAG_TRST_L_PD: J1.1 R61.1 R69.1 R70.2 U1.P4(JTG_TRST_L)
OCT_MSC_CLKOUT: TP4.1 U1.AB12(MSC_CLKOUT)
OCT_MSC_CLKOUT_EN: R72.1 SW1.1(A0) U1.AB11(MSC_CLKOUT_ENABLE)
OCT_MSC_SYS_CLKOUT: TP3.1 U1.AA8(MSC_SYS_CLKOUT)
OCT_PLL_MUL0: R830.1(A[0]) U1.W1(PLL_MUL_0/GPIO_13) ; also on sheet 17
OCT_PLL_MUL1: R831.1(A[0]) U1.W2(PLL_MUL_1/GPIO_14) ; also on sheet 17
OCT_PLL_MUL2: R832.1(A[0]) U1.W5(PLL_MUL_2/GPIO_15) ; also on sheet 17
OCT_PLL_MUL3: R833.1(A[0]) U1.W6(PLL_MUL_3/GPIO_16) ; also on sheet 17
OCT_PLL_MUL4: R835.1(A[0]) U1.W7(PLL_MUL_4/GPIO_17) ; also on sheet 17
OCT_PLL_MUL5: R834.1(A[0]) U1.Y1(PLL_MUL_5/GPIO_18) ; also on sheet 17
OCT_QLMC_REF_CLK0_N: R55.2 U1.AF19(DLMC_REF_CLK0_N)
OCT_QLMC_REF_CLK0_P: R54.2 U1.AE19(DLMC_REF_CLK0_P)
OCT_RESET_L: U1.P7(CHIP_RESET_L) ; also on sheet 32
OCT_SYS_PLL_PMUL0: R826.1(A[0]) U1.Y2(SYS_PLL_MUL_0/GPIO_19) ; also on sheet 17
OCT_SYS_PLL_PMUL1: R827.1(A[0]) U1.Y3(SYS_PLL_MUL_1/GPIO_20) ; also on sheet 17
OCT_SYS_PLL_PMUL2: R828.1(A[0]) U1.Y4(SYS_PLL_MUL_2/GPIO_21) ; also on sheet 17
OCT_SYS_PLL_PMUL3: R829.1(A[0]) U1.Y5(SYS_PLL_MUL_3/GPIO_22) ; also on sheet 17
OCT_SYS_PLL_PMUL4: R907.1(A[0]) U1.Y6(SYS_PLL_MUL_4/GPIO_23) ; also on sheet 17
OCT_TEMP_EVENT: R821.1(A[0]) ; also on sheet 46
OCT_THERMAL_D_N: U1.AF12(THERMAL_D_N) ; also on sheet 18
OCT_THERMAL_D_P: U1.AF13(THERMAL_D_P) ; also on sheet 18
OCT_THERMAL_TRIP_L: R59.1 U1.AC8(THERMAL_TRIP_L) ; also on sheet 37
OCT_TIVA_JTAG_TDO: R931.2 ; also on sheet 39
OCT_TWS1_SCL: U3.8(B1) ; also on sheet 18 26 27 48 52 53
OCT_TWS1_SDA: U3.1(B2) ; also on sheet 18 26 27 48 52 53
OCT_USB_TRST_L: J1.2 R60.2 U1.N3(JTG_USB_TRST_L)
PLL_REF_CLK_50M: R57.1 U1.AF9(PLL_REF_CLK)
POWER_TEMP_EVENT0: R817.1(A[0]) ; also on sheet 46
POWER_TEMP_EVENT1: R818.1(A[0]) ; also on sheet 46
R_IRQ_INTRPT: R853.1(A[0]) ; also on sheet 42
RTC_IRQ: U1.AC2(PBUS_AD_23/GPIO_39) ; also on sheet 18
SD_EMMC_SEL: R2.1 ; also on sheet 49
SOC_TRXFE_GPIO1: U1.AA5(PBUS_CLE/GPIO_29) ; also on sheet 47
SOC_TRXFE_GPIO2: U1.AA6(PBUS_WE_L/GPIO_30) ; also on sheet 47
SOC_TRXFE_GPIO3: U1.AA7(PBUS_DIR/GPIO_31) ; also on sheet 47
SOC_TRXFE_GPIO4: U1.AB1(PBUS_AD_16/GPIO_32) ; also on sheet 47
SOC_TRXFE_GPIO5: U1.AB2(PBUS_AD_17/GPIO_33) ; also on sheet 47
SOC_TRXFE_GPIO6: U1.AB3(PBUS_AD_18/GPIO_34) ; also on sheet 47
SPI_PROG_SEL: U1.Y7(PBUS_ALE_1/GPIO_24) ; also on sheet 24
SuperCap_VCC: C880.1 J28.5 U87.7(IN2_1) U87.8(IN2_2)
TIVA_2GMODULE_PWR_ON: R702.2 R815.1(A[0]) ; also on sheet 42
TIVA_JTAG_RESET: R933.2 ; also on sheet 39 40
TIVA_JTAG_TCK: R937.2 ; also on sheet 37 39
TIVA_JTAG_TMS: R935.2 ; also on sheet 37 39
TIVA_OCT_GPIO1: U1.AD1(PBUS_AD_25/GPIO_41) ; also on sheet 37
TIVA_OCT_GPIO2: U1.AD2(PBUS_AD_26/GPIO_42) ; also on sheet 37
TIVA_OCT_GPIO3: U1.AD3(PBUS_AD_27/GPIO_43) ; also on sheet 37
TIVA_OCT_GPIO4: U1.AD4(PBUS_AD_28/GPIO_44) ; also on sheet 37
TIVA_OCT_JTAG_TDI: R928.2 ; also on sheet 39
TIVA_PWRMNTR_I2C6_SCLK: U80.25(SCL) U89.25(SCL) ; also on sheet 28 29 31 37 38 43
TIVA_PWRMNTR_I2C6_SDA: U80.24(SDA) U89.24(SDA) ; also on sheet 28 29 31 37 38 43
TIVA_RESET: U80.23(NRESET) U89.23(NRESET) ; also on sheet 38 40 48
TIVA_SYNCCONN_GPIO1: R816.1(A[0]) ; also on sheet 42
TIVA_USER_LED1: R822.1(A[0]) ; also on sheet 39
TIVA_USER_LED2: R823.1(A[0]) ; also on sheet 39
TRXFE_PWR_ALRT: R840.1(A[0]) ; also on sheet 31
UART_SEL: R1.1 R915.2 ; also on sheet 25 37
USER_LED0: J33.1 R8.1 U1.AB4(PBUS_AD_19/GPIO_35) U100.3(IO2)
USER_LED1: J33.2 R9.1 U1.AB5(PBUS_AD_20/GPIO_36) U100.1(IO1)
USER_LED2: J33.3 R10.1 U1.AB6(PBUS_AD_21/GPIO_37) U100.6(IO4)
VREF_DDR: C14.1 C15.1 C16.1 C17.1 C18.1 C19.2 U2.164(VREFCA) ; also on sheet 30
VRM_DISABLE_GPIO_9: R73.1 U1.V4(VRM_DISABLE/GPIO_9)
VTT_DDR: C8.1 C9.1 C10.1 C11.1 C12.1 C13.2 U2.258(VTT) ; also on sheet 30
N21187158: R68.2 U1.AF8(EFUSE_PROG)
N25937714: Q1.G R8.2
N25937863: Q2.G R9.2
N25937983: Q3.G R10.2
N25937997: D3.K Q3.D
N25937999: D3.A R5.1
N25952323: D6.A R58.1
N25952325: D6.C Q6.D
N25952344: Q6.G R59.2
N26707527: Q4.G R11.2
N26707550: D4.K Q4.D
N26707552: D4.A R6.1
N26709495: D5.K Q5.D
N26709497: D5.A R7.1
N26709516: Q5.G R12.2
N27957448: J2.2 R69.2
N27957616: J2.19 R74.2
N27957621: J2.17 R75.2
N27957628: J2.11 R76.2
N29302827: R2.2 U1.AC5(PBUS_AD_24/GPIO_40)
N30939906: R28.1 U3.6(OE)
N31030205: R56.1 X1.1(EN)
N32670267: D1.K Q1.D
N32670269: D1.A R3.1
N32670277: D2.K Q2.D
N32670279: D2.A R4.1
N33130253: R811.2(B[0]) U89.10(ADDR1)
N33130257: R812.1(A[0]) U89.26(ADDR0)
N33130275: R809.1(A[0]) R810.2(B[0]) U89.9(#INT)
N33132313: R693.2(B[0]) U80.10(ADDR1)
N33132317: R694.2(B[0]) U80.26(ADDR0)
N33132335: R695.2(B[0]) R698.1(A[0]) U80.9(#INT)
N33132367: R853.2(B[0]) U80.22(I/O[15])
N33133035: R813.2(B[0]) U80.27(I/O[0])
N33133042: R814.2(B[0]) U80.28(I/O[1])
N33133049: R815.2(B[0]) U80.1(I/O[2])
N33133062: R816.2(B[0]) U80.2(I/O[3])
N33133064: R817.2(B[0]) U80.5(I/O[4])
N33133066: R818.2(B[0]) U80.6(I/O[5])
N33133083: R819.2(B[0]) U80.7(I/O[6])
N33133085: R820.2(B[0]) U80.8(I/O[7])
N33133087: R821.2(B[0]) U80.13(I/O[8])
N33133104: R822.2(B[0]) U80.14(I/O[9])
N33133106: R823.2(B[0]) U80.15(I/O[10])
N33133108: R824.2(B[0]) U80.16(I/O[11])
N33133120: R825.2(B[0]) U80.19(I/O[12])
N33133483: U89.2(I/O[3]) U92.9(4A)
N33133501: U89.6(I/O[5]) U93.1(1A)
N33133503: U89.7(I/O[6]) U93.3(2A)
N33135240: R842.2(B[0]) U80.20(I/O[13])
N33135247: R843.2(B[0]) U80.21(I/O[14])
N33150729: R855.2 TP72.1 U87.14(~{STAT1})
N33150734: R854.2 TP73.1 U87.11(~{STAT2})
N33561516: R826.2(B[0]) U92.2(1Y)
N33561517: R828.2(B[0]) U92.6(3Y)
N33561518: R827.2(B[0]) U92.4(2Y)
N33561519: R829.2(B[0]) U92.8(4Y)
N33561656: U89.27(I/O[0]) U92.1(1A)
N33561670: U89.28(I/O[1]) U92.3(2A)
N33561684: U89.1(I/O[2]) U92.5(3A)
N33562585: R830.2(B[0]) U93.2(1Y)
N33562586: R832.2(B[0]) U93.6(3Y)
N33562587: R834.2(B[0]) U93.12(6Y)
N33562588: R831.2(B[0]) U93.4(2Y)
N33562589: R833.2(B[0]) U93.8(4Y)
N33562590: R835.2(B[0]) U93.10(5Y)
N33562892: U89.8(I/O[7]) U93.5(3A)
N33562908: U89.13(I/O[8]) U93.9(4A)
N33562917: U89.14(I/O[9]) U93.11(5A)
N33563064: R836.2(B[0]) U94.2(1Y)
N33563065: R839.2(B[0]) U94.8(4Y)
N33563067: R838.2(B[0]) U94.6(3Y)
N33563069: R837.2(B[0]) U94.4(2Y)
N33563256: U89.15(I/O[10]) U93.13(6A)
N33563260: U89.16(I/O[11]) U94.1(1A)
N33563695: U89.19(I/O[12]) U94.3(2A)
N33563704: U89.20(I/O[13]) U94.5(3A)
N33563995: R840.2(B[0]) U89.22(I/O[15])
N33585311: R907.2(B[0]) U92.10(5Y)
N33585314: U89.5(I/O[4]) U92.11(5A)
N33585473: U89.21(I/O[14]) U94.9(4A)
N33619419: R911.2 U1.AE2(PBUS_AD_29/GPIO_45)
N33646472: R915.1 U1.AA2(PBUS_CE_0_L/GPIO_26)

Not connected (* = marked no-connect by the designer): J28 3* 4*; MH13 1*; MH16 1*; U1 AE7(EFUSE_ENABLE_L); U2 162(C0/CS2_N/NC)* 165(C1/CS3_N/NC)*; U80 11(OSCIO)*; U87 12(~{WARN2})* 13(~{WARN1})*; U89 11(OSCIO)*; U92 12(6Y)* 13(6A)*; U94 10(5Y)* 11(5A)* 12(6Y)* 13(6A)*; U100 4(IO3)* 5(VCC)*

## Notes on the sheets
sheet 1
- 0
- 0
- 0
- coprocessor clock
- 1
- 0
- 0
- 0
- core clock
- 0
- 1
- 1
- 0
- 1
- bootmethod
- 0
- 1
- 0
- ADDRESS-70
- ADDRESS-71
sheet 2
- when V1 fall to 3.0V ,V2 on
- when V1 raise to 3.2V ,V2 off
- calculate the resistor
- MH13 should place 1.5inch away from J28
- J28
- MH13
- 9774070243R
sheet 3
- CN8100-GBCv2
sheet 4
- TABLE OF CONTENTS
- PAGE
- TITLE OF PAGE
- PAGE
- TITLE OF PAGE
- PAGE
- TITLE OF PAGE
- P.01
- COVER PAGE
- P.26
- BOOT SPI FLASH & NAND
- P.51
- TIVA OCT- IO ISOLATION
- P.02
- TABLE OF CONTENTS
- P.27
- OCT-UART0
- P.52
- Trusted Platform Module
- P.03
- REVISION HISTORY
- P.28
- DLM2_0 TO MINI PCIE
- P.53
- IO-Expander
- P.04
- FUNCTIONAL BLOCK DIAGRAM
- P.29
- DLM2_1 TO MINI PCIE
- P.54
- SuperCap Back-Up
- P.05
- POWER BLOCK DIAGRAM
- P.30
- POWER ENTRY
- P.55
- P.06
- POWER UP SEQUENCE
- P.31
- CONTLR : CPU CORE & 3V3
- P.56
- P.07
- CLOCK ARCHITECTURE
- P.32
- GATE DRVRS : CORE & 3V3
- P.57
- P.08
- CNOCT GPIO
- P.33
- V3P3_TIVA & 5V REG
- P.58
- P.09
- CNOCT DDR4
- P.34
- V0P9_DLM & V1P2_DDR
- P.59
- P.10
- CNOCT DLM3:0, RGMII
- P.35
- V1P2,V2P5,V0P9_ PLL
- P.60
- P.11
- CNOCT CONFIGURATION
- P.36
- POWER AND RESET SEQUENCING
- P.61
- P.12
- CNOCT MISCELLANEOUS I/O
- P.37
- POWER UP SEQUENCE
- P.62
- P.13
- CNOCT CORE VDD
- P.38
- CLOCK DISTRIBUTIONS 1
- P.63
- P.14
- CNOCT I/O & MISC VDD
- P.39
- CLOCK DISTRIBUTIONS 2
- P.64
- P.15
- CNOCT QLM & USB SUPPLY
- P.40
- TIVA ETHERNET
- P.65
- P.16
- CNOCT GND
- P.41
- TIVA IO'S
- P.17
- CNOCT CORE & DDR DECOUPLING CAPS
- P.42
- TIVA POWER
- P.18
- CNOCT STRAPPING
- P.43
- TIVA JTAG CONNECTOR&ICD&LED
- P.19
- RTC & THERMAL SENSORS
- P.44
- TIVA FLASH & RESET
- P.20
- ETHERNET SWITCH
- P.45
- EEPROM
- BOARD TO BOARD CONNECTOR
- P.21
- ETHERNET SWITCH POWER
- P.46
- P.22
- RJ45 PORT0-PORT1-PORT5
- P.47
- mSATA Connector0
- P.23
- USB2514BI-USB HUB
- P.48
- mSATA Connector1
- P.24
- ETH PORT3 TO BB
- P.49
- PTP Module
- P.25
- BOOT EMMC /MMC
- P.50
- Thermal Sensor & Light Sensor
sheet 5
- REVISION HISTORY
- REV
- DESCRIPTION
- DATE
- REV
- DESCRIPTION
- DATE
- 1.0
- initial version
- 2017-12-12
- 1.2
- 1. Remove V5P0_EN,V3P3_EN from TIVA to U33,U28 respectively,
  2.delete R767,R916, Place R339
  3.Delete R910 ,Connect R368 to V3P3
  4.Delete net: SATA0_LED_N,SATA1_LED_N,
  5.add R918,R919  0ohm
  6.Connect TIVA PP0,PP1 to J31 as UART IF
  7,Connect TIVA_FE_RESET_OUT to TIVA PM2
  8.Connect TIVA_USER_LED1/2 to IO expander
  9.use TIVA PD0/PD1 as IIC7,connect to LED board, add R920,R921 2.2k
  10.Add U96,U97
  11. Add U95 related circult for IIC isolation
- 2018-5-11
- 1.1
- 1.modfiy ethernet swith to KSZ9897R
  2. modify clk distribution to microsemi solution
- 2018-1-18
- 3. add power supply(1.2V,2.5V)  for KSZ9897R
- 1.1.1
- 1. change ddr4 to  DDR4 SO-DIMM
- 2.update reset squence and spi flash,delete boot nand
- 2018-3-12
- 2018-3-13
- 3.add TPM ,modify SPI connection
- 1.2.1
- 1.modify T1 connection order for easily layout
  2.modify U59~U62 pin order for easily layout
  3.add jtag chain,R925~R937 0ohm for jtag chain
  4.add D46,D47 ESD protection diode
- 2018-5-15
- 1. updated the packages of many part
  2. add IDT PTP module
  3. modify uart,iic etc.
- 2018-3-14
- 1.2.2
- 1.Add TRXFE_DET net  for BB board present detection
  2.add TIVA waken function page42
- 1.1.2
- 4. add power monitor,temp sensor etc
- 2018-5-17
- 1.1.3
- 1. delete the LT8640  and ORING power switch, page30
  2. add power block diagram page5
  3.connect tiva_syncconn_gpio1 to U82
  4.modify some error of offpage connector name
  5.add isolation between SDR and TIVA/SOC
  6.add function block diagram page4
- 1.2.3
- 1.add EBMP feature at page8, add U100,J33
- 2018-5-25
- 2018-3-29
- 1.change R407 to 10K
  2. Modify U28 part Number to MP2951-0067-Z
  3.change U97,U97 to DNP
  4.Modify msata rx lane polarity
- 1.1.4
- 1.update the iic device of tiva in blockdiagram and circult,page3
  2.modify PTP connection accord IDT recommendations.page49
  3.add OCT power control switch and 2pin header  at page30.
  4.add two eeprom for TIVA saving ID,inventory. page45
  5.update the pcb_footprint of all components
  6. remove LT8640 at page30
- 2.0
- 2018-7-14
- 2018-3-30
- 1.modify C325,C326 to DNP
  2.Modify X2 part number
- 2.1
- 2018-7-18
- 1.Modify  some part's pin name to generate list rightlly(U9,U86,U22-U25)
  2.reannotate the part's reference
  3. Don't place R178
  4.update uSD connector
  5.Add MTGHOLE at page52.
  6.modified schemaitc accoard the excel review list v1.6,
  7.update table content
  8.modify ethsw to KSZ9897S,,add R769page 20,21
    add SGMII path from ethsw to octeon.dlm1  ,page20
    through out  PME signal to TIVA,page20
    through out IBA signal to TIVA,page20
  9.delete TRXFE power ,page35,
  As will powering RF through   separate
   cable from power board T
  10,change R312 TO 150K
  11. modify the errors according the review list ver0.17
  12. modifiy KSZ9897S to KSZ9567S,Add syncE option. page20
  13. modify errors on ksz9897s base MicroChip's review, page20
  14, add syncE option ,page49.
- 1.1.5
- 2018-4-11
- 1.1.6
- 1.add series resistor,R777~R780, at page40
  2.Modifiy some resistor to DNP, at page51
  3. modify some component's footprint,and part-number
  4.modify JTB1 pin2,pin3 to V12P0, JTB1 pin5,pin4 to GND,page30
  5.Modify S1 same as S2, Modify RJ45/J10/JTAG  pcb_foorprint.
  6.delete the no-used connection to Rsvd-pin on mini-pcie.page28,page29
  7.modify BT1 same with BT2
- 2018-4-20
- 1.update power block,page4
  2. add 12V backup related circult (LTC4419), page30,
  3.add super cap for tiva/tpm/ir, page54
  4.add IR sensor,
  5.delete T2,J27, modify ethsw port1,port2 connect to FX18-40s-0.8sh .
  6.add U89, page53,
  7. modify OCT strapping resistor, connect PLL configuration to U89,page53
  8,connect BOOT method configer to U89 page53
- 1.1.7
- 2018-4-23
- 1.1.8
- 1.add USB hub
  2.add 0ohm resistor(package=25120 for DVT test)
  3.modify J13,J15 pcb footprint
  4.Delete D13~D15,C485,C486,C488
  5.change J2 package
  6,add J32,Buzzer circult
         add led:D34,D35,D36,D39,D40,D41,D42,D43,D44,D45
  7,Add MH2,MH3
  8.modify default boot method to SPI
  9.modify J3M2 PCB Footprint with mount ing hole
  10.add c908,c909
- 2018-4-27
- 1. add U92 ,U93,U94,C910~C912
  2.add JP2,R908
  3.bring back U38,U39 related circuit  for TRXFE_12V  at page35
- 1.1.9
- 2018-5-4
- 1.1.10
- 1.add R909,R910,R911,R912,R913,R914,R915,R916,R917
  2.modify MH16 pcb footprint,
  3.modify some error net
- 2018-5-7
- 1.1.11
- 1.Change R796.1 to GND, setting core clock defult 1.5G(Since the CPU max speed is1.5Ghz)
- 2018-5-9
sheet 6
- SM802283
- 0X68
- RTC
- JTAG
- 2.5V
- 1.2V
- 50M
- 125M
- 25M
- 0X4C
- FAN
  CTRL
- OCT_RESET
- DC-OK
- 0X54
- EEPROM
- RJ45 port5
- JTAG
- PLL_CLK
- RGMII
- DDR-CLK
- DLMC,DLM0-3 CLK
- TPM
- MUX
- TRANS
- port5
- SPI
- TIVA-I2C2
- I2C1
- SPI
- SPI FLASH
- KSZ9567S
- SGMII
- EMMC
- RJ45 port0
- RGMII
- SGMII(BGX0)
- EMMC
- EMMC
  FLASH
- port1
- port2
- USB
  connector
- usb2.0
- RGMII
- RJ45 port1
- port4
- port7
- FT232
- MUX
- UART0
- SD CARD
- port6
- FX18-40S-0.8SH
- port3
- mPCIE0
- LMC
- DDR4 72bit ECC
- DDR4-
  SODIMM
- mPCIE1
- CN81XX
- MP2951
- HUB
- USB2.0
- Transformer
- Transformer
- I2C0
- 0X20
- DLM3
- mSATA
- mSATA x 2
- Transformer
- UART
- USB2.0
- I2C0
- DLM2
- PCIE  2 x 1lane
- mPCIE x 2
- ETH
- ETH
- SPI FLASH
- SPI
- SPI 1
- I2C0
- I2C0
- 1pps IN
- 0X18
- temp sensor
- I2C1
- TIVA
- GPIO
- GPIO
- GPIO x 4
- GPIO45
- 1pps OUT
- PTP Module
- TCXO
  25M
- Transformer
- 0X19
- temp sensor
- GPIO47
- CLK OUT
- I2C6
- INA226
- 0X40
- USB3.0
- GPIO46
- 0X1A
- temp sensor
- INA226
- 0X41
- DLM0
- 0X1B
- temp sensor
- GPIO
- I2C8
- I2C4
- I2C3
- I2C2
- INA226
- 0X42
- PCIE 1 x1 lane
- JTAG
- I2C8
- GPIO
- INA226
- 0X44
- TRXFE_12V
- INA226
- 0X45
- USB3.0
- I2C4
- I2C3
- I2C2
- TIVA_SYNC_INT
- BB_SENSOR_ALRT
- FE_SENSOR_ALRT
- IO-Exp
- 0X71
- GPIO1:6
- PCIE-CLK-100M
- I2C8
- UART4
- FE_PWR_CTRL
- 2G-MODULE
- SYNC
- FE_RESET
- TRXFE_RESET
- IO-EXP
- 0X70
- 0x1A
- temp sensor
- ?
- LED board
- eepromx2
- 0XA0/0XA1
- SDR
  connector
- ICD TEST CONNECTOR
- Need confirm and discuss
sheet 10
- ADD FOR EBMP
sheet 11
- PLACE THESE RESISTORS
  CLOSE TO CPU BGA VIAS
- VCCB >= VCCA
- DIMM DE-COUPLING CAPS
- confirm the IIC?
sheet 12
- NOTE: PLACE PARALLEL TERMINATIONS AS
  CLOSE AS POSSIBLE TO CPU BALLS
- HCSL CLOCK
- If Jtag chain:
- place R928,R931,R933,R935,R937
- remove R929 R930,R932,R934,R936
